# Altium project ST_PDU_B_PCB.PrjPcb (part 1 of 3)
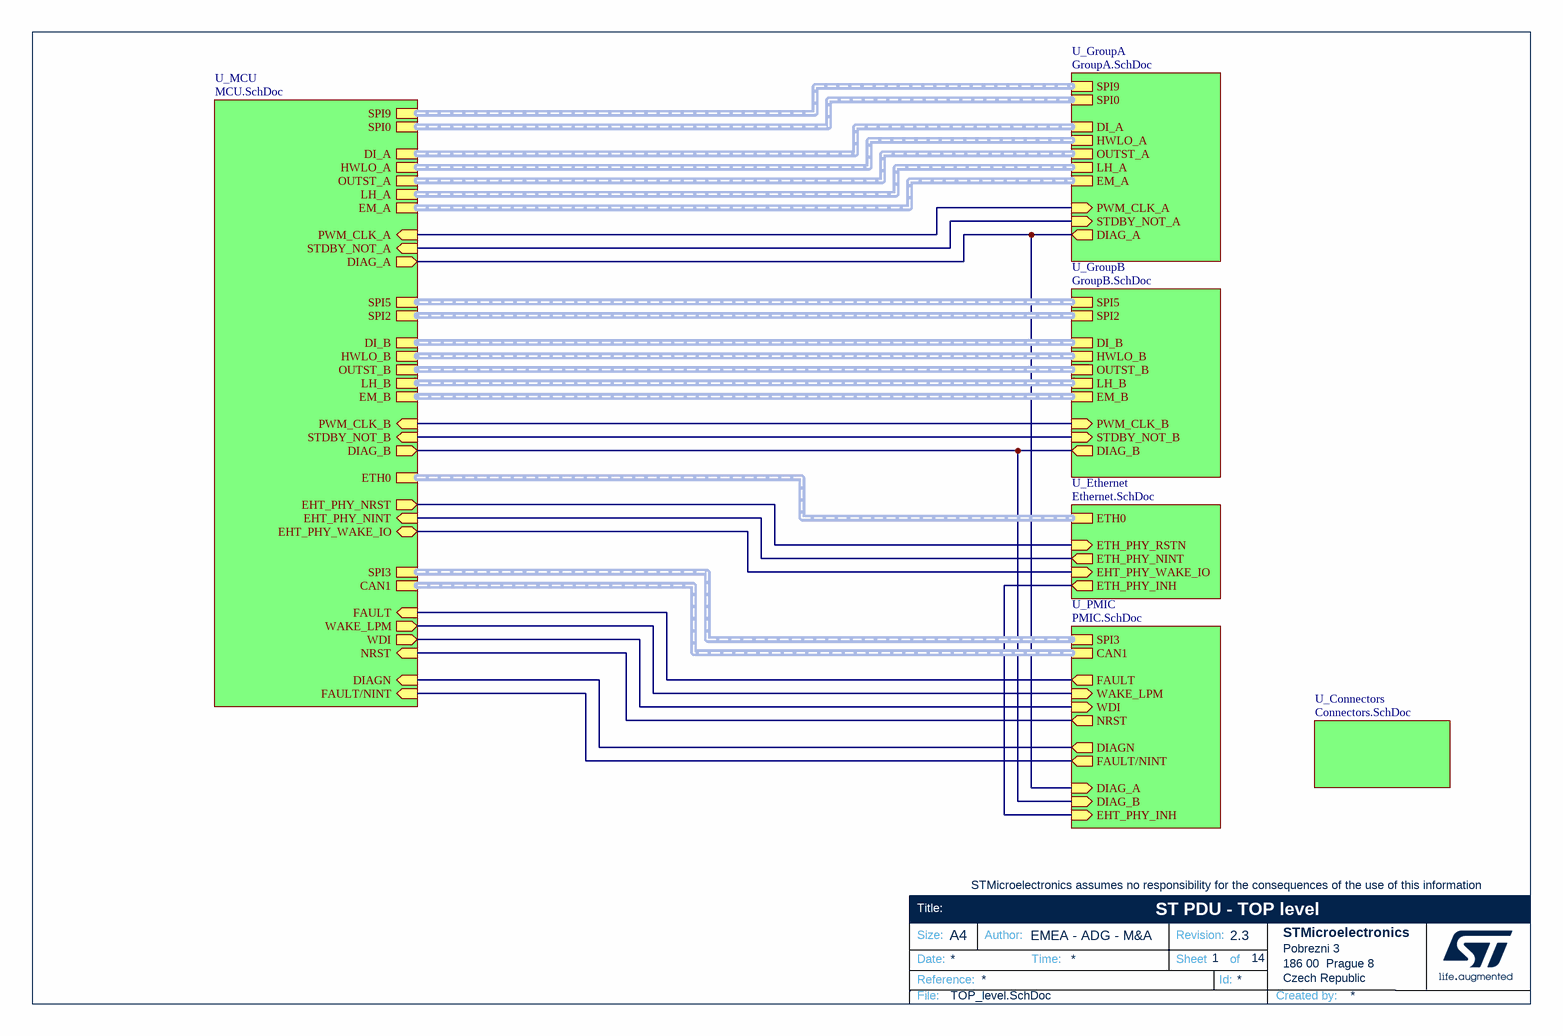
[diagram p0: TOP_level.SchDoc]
14 sheets, 872 parts. Net scope: hierarchical (ports join the sheet entries above them; power ports are global).
Board file: ST_PDU_B_PCB.PcbDoc
Sheets:
  TOP_level.SchDoc
    U_GroupA = GroupA.SchDoc
      U_VNF1248+8F8_A1 = VNF1248+8F8.SchDoc
      U_VNF1248+5F8_A1 = VNF1248+5F8.SchDoc
      U_VNF1248+3F8_A1 = VNF1248+3F8.SchDoc
      U_VNF1248+3F8_A2 = VNF1248+3F8.SchDoc
      U_VNF1248+3F8_A3 = VNF1248+3F8.SchDoc
      U_VNF9D1M5Q_A1 = VNF9D1M5Q.SchDoc
      U_VNF9D1M5Q_A2 = VNF9D1M5Q.SchDoc
      U_L99SP08_A1 = L99SP08.SchDoc
      U_VNF9Q20SF_A1 = VNF9Q20SF.SchDoc
    U_GroupB = GroupB.SchDoc
      U_VNF1248+8F8_B1 = VNF1248+8F8.SchDoc
      U_VNF1248+5F8_B1 = VNF1248+5F8.SchDoc
      U_VNF1248+3F8_B1 = VNF1248+3F8.SchDoc
      U_VNF1248+3F8_B2 = VNF1248+3F8.SchDoc
      U_VNF1248+3F8_B3 = VNF1248+3F8.SchDoc
      U_VNF9D1M5Q_B1 = VNF9D1M5Q.SchDoc
      U_VNF9D1M5Q_B2 = VNF9D1M5Q.SchDoc
      U_L99SP08_B1 = L99SP08.SchDoc
      U_VNF9D5SF_B1 = VNF9D5SF.SchDoc
      U_VNF9D5SF_B2 = VNF9D5SF.SchDoc
    U_MCU = MCU.SchDoc
    U_PMIC = PMIC.SchDoc
    U_Ethernet = Ethernet.SchDoc
    U_Connectors = Connectors.SchDoc

## Sheet TOP_level.SchDoc: ST PDU - TOP level
size A4; Author: EMEA - ADG - M&A; Organization: STMicroelectronics; Address1: Pobrezni 3; Address2: 186 00  Prague 8; Address3: Czech Republic; Revision: 2.3; SheetNumber: 1; SheetTotal: 14

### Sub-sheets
U_Connectors = Connectors.SchDoc: no entries
U_Ethernet = Ethernet.SchDoc: ETH0 (harness ETH0), ETH_PHY_RSTN (in), ETH_PHY_NINT (out), EHT_PHY_WAKE_IO (in), ETH_PHY_INH (out)
U_GroupA = GroupA.SchDoc: SPI9 (harness SPI9), SPI0 (harness SPI0), HWLO_A (harness HWLO_A), DI_A (harness DI_A), OUTST_A (harness OUTST_A), DIAG_A (out), STDBY_NOT_A (in), PWM_CLK_A (in), LH_A (harness LH_A), EM_A (harness EM_A)
U_GroupB = GroupB.SchDoc: SPI2 (harness SPI6), SPI5 (harness SPI5), HWLO_B (harness HWLO_B), DI_B (harness DI_B), OUTST_B (harness OUTST_B), DIAG_B (out), STDBY_NOT_B (in), PWM_CLK_B (in), LH_B (harness LH_B), EM_B (harness EM_B)
U_MCU = MCU.SchDoc: SPI9 (harness SPI9), SPI0 (harness SPI0), HWLO_A (harness HWLO_A), DI_A (harness DI_A), OUTST_A (harness OUTST_A), DIAG_A (out), STDBY_NOT_A (in), PWM_CLK_A (in), LH_A (harness LH_A), EM_A (harness EM_A), SPI2 (harness SPI6), SPI5 (harness SPI5), HWLO_B (harness HWLO_B), DI_B (harness DI_B), OUTST_B (harness OUTST_B), DIAG_B (out), STDBY_NOT_B (in), PWM_CLK_B (in), LH_B (harness LH_B), EM_B (harness EM_B), ETH0 (harness ETH0), SPI3 (harness SPI3), CAN1 (harness CAN1), NRST (in), FAULT (in), WAKE_LPM (out), WDI (out), DIAGN (in), FAULT/NINT (in), EHT_PHY_NRST (out), EHT_PHY_WAKE_IO (bidir), EHT_PHY_NINT (in)
U_PMIC = PMIC.SchDoc: NRST (out), FAULT (out), WAKE_LPM (in), WDI (in), SPI3 (harness SPI3), CAN1 (harness CAN1), DIAGN (out), FAULT/NINT (out), DIAG_A (in), DIAG_B (in), EHT_PHY_INH (in)

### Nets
DIAG_A: sheet U_GroupA/DIAG_A, sheet U_MCU/DIAG_A, sheet U_PMIC/DIAG_A
DIAG_B: sheet U_GroupB/DIAG_B, sheet U_MCU/DIAG_B, sheet U_PMIC/DIAG_B
DIAGN: sheet U_MCU/DIAGN, sheet U_PMIC/DIAGN
ETH_INH: sheet U_PMIC/EHT_PHY_INH, sheet U_Ethernet/ETH_PHY_INH
ETH_PHY_NINT: sheet U_MCU/EHT_PHY_NINT, sheet U_Ethernet/ETH_PHY_NINT
ETH_PHY_NRST: sheet U_MCU/EHT_PHY_NRST, sheet U_Ethernet/ETH_PHY_RSTN
ETH_PHY_WAKE_IO: sheet U_MCU/EHT_PHY_WAKE_IO, sheet U_Ethernet/EHT_PHY_WAKE_IO
FAULT: sheet U_MCU/FAULT, sheet U_PMIC/FAULT
FAULT/NINT: sheet U_MCU/FAULT/NINT, sheet U_PMIC/FAULT/NINT
NRST: sheet U_MCU/NRST, sheet U_PMIC/NRST
PWM_CLK_A: sheet U_GroupA/PWM_CLK_A, sheet U_MCU/PWM_CLK_A
PWM_CLK_B: sheet U_GroupB/PWM_CLK_B, sheet U_MCU/PWM_CLK_B
STDBY_NOT_A: sheet U_GroupA/STDBY_NOT_A, sheet U_MCU/STDBY_NOT_A
STDBY_NOT_B: sheet U_GroupB/STDBY_NOT_B, sheet U_MCU/STDBY_NOT_B
WDI: sheet U_MCU/WDI, sheet U_PMIC/WDI
WK_LPM: sheet U_MCU/WAKE_LPM, sheet U_PMIC/WAKE_LPM

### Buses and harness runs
harness sheet U_Ethernet/ETH0 = sheet U_MCU/ETH0
harness sheet U_GroupA/DI_A = sheet U_MCU/DI_A
harness sheet U_GroupA/EM_A = sheet U_MCU/EM_A
harness sheet U_GroupA/HWLO_A = sheet U_MCU/HWLO_A
harness sheet U_GroupA/LH_A = sheet U_MCU/LH_A
harness sheet U_GroupA/OUTST_A = sheet U_MCU/OUTST_A
harness sheet U_GroupA/SPI0 = sheet U_MCU/SPI0
harness sheet U_GroupA/SPI9 = sheet U_MCU/SPI9
harness sheet U_GroupB/DI_B = sheet U_MCU/DI_B
harness sheet U_GroupB/EM_B = sheet U_MCU/EM_B
harness sheet U_GroupB/HWLO_B = sheet U_MCU/HWLO_B
harness sheet U_GroupB/LH_B = sheet U_MCU/LH_B
harness sheet U_GroupB/OUTST_B = sheet U_MCU/OUTST_B
harness sheet U_GroupB/SPI2 = sheet U_MCU/SPI2
harness sheet U_GroupB/SPI5 = sheet U_MCU/SPI5
harness sheet U_MCU/CAN1 = sheet U_PMIC/CAN1
harness sheet U_MCU/SPI3 = sheet U_PMIC/SPI3

## Sheet GroupA.SchDoc: ST PDU - Group A
size A3; Author: EMEA - ADG - M&A; Organization: STMicroelectronics; Address1: Pobrezni 3; Address2: 186 00  Prague 8; Address3: Czech Republic; Revision: 2.3; SheetNumber: 2; SheetTotal: 14
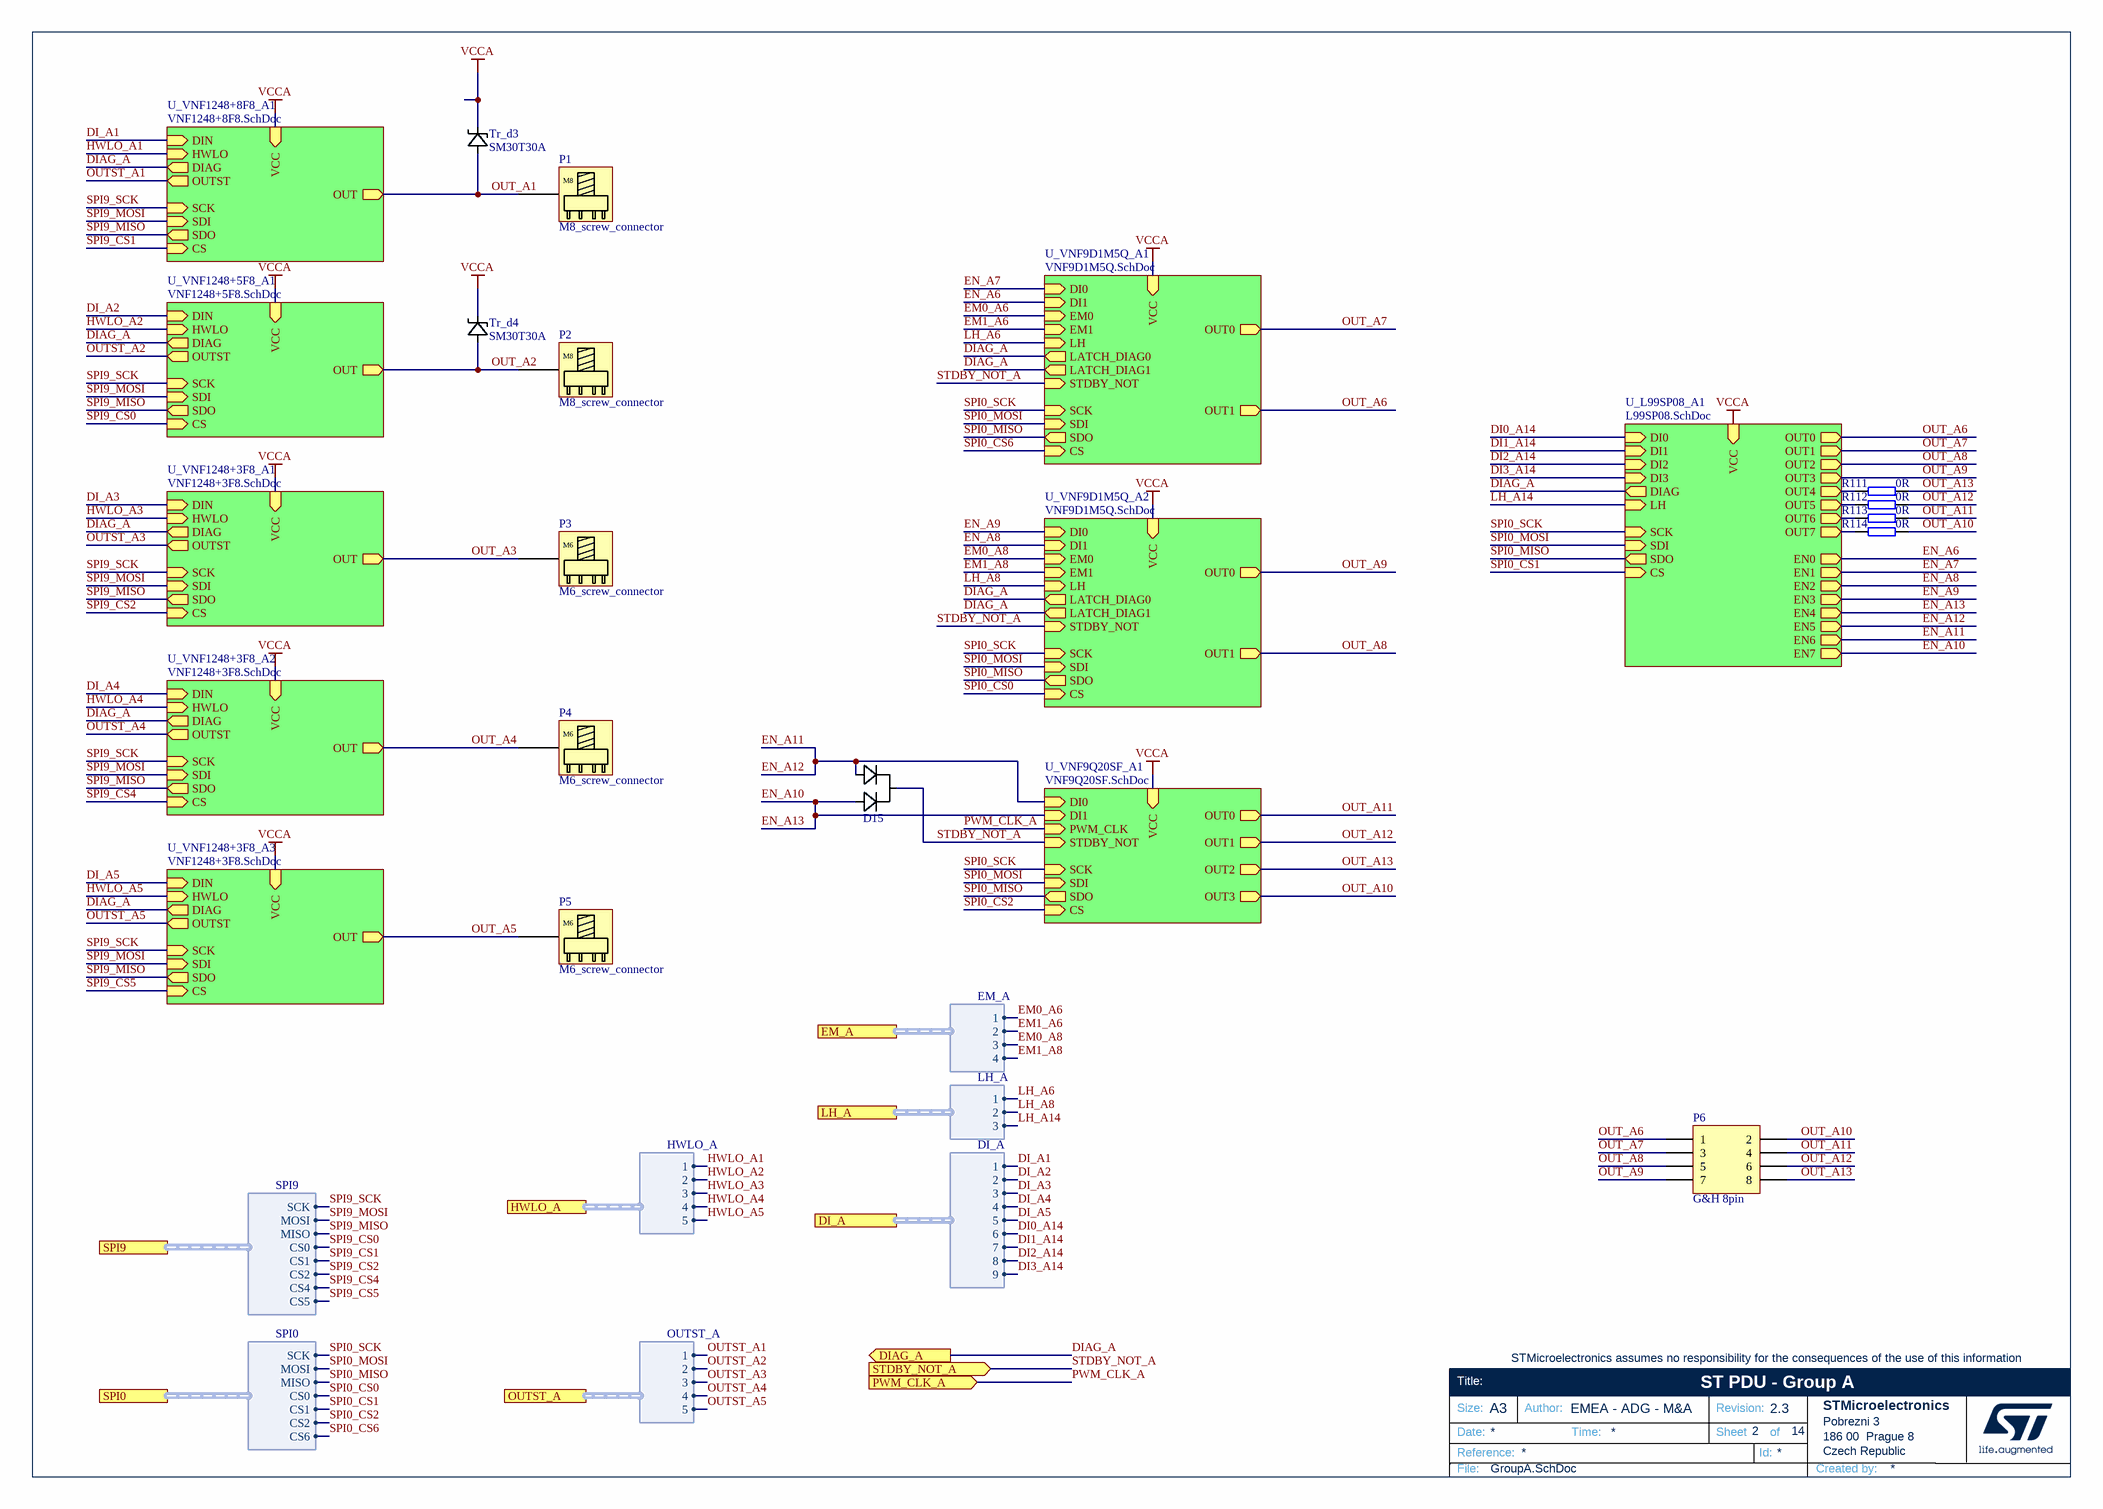
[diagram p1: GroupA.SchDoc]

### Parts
D15  BAT54-Y  [SOT323-3L_STM]  (value not drawn)
P1  M8_screw_connector  [MTConn Power Tower M8]
P2  M8_screw_connector  [MTConn Power Tower M8]
P3  M6_screw_connector  [MTConn Power Tower M6]
P4  M6_screw_connector  [MTConn Power Tower M6]
P5  M6_screw_connector  [MTConn Power Tower M6]
P6  value G&H 8pin  [MTConn GH 8pin]  (hidden comment: GH 8pin)
R111  0R  [R0603_round]
R112  0R  [R0603_round]
R113  0R  [R0603_round]
R114  0R  [R0603_round]
Tr_d3  SM30T30A  [SMC]
Tr_d4  SM30T30A  [SMC]

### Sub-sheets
U_L99SP08_A1 = L99SP08.SchDoc: CS (in), SCK (in), SDI (in), SDO (out), OUT1 (out), OUT2 (out), OUT3 (out), OUT0 (out), DI0 (in), DI1 (in), DI2 (in), DI3 (in), LH (in), DIAG (out), VCC (in), EN1 (out), EN2 (out), EN3 (out), EN0 (out), EN5 (out), EN6 (out), EN7 (out), EN4 (out), OUT5 (out), OUT6 (out), OUT7 (out), OUT4 (out)
U_VNF9D1M5Q_A1 = VNF9D1M5Q.SchDoc: CS (in), OUT0 (out), OUT1 (out), SCK (in), SDI (in), SDO (out), EM0 (in), EM1 (in), DI0 (in), DI1 (in), LATCH_DIAG0 (out), LATCH_DIAG1 (out), LH (in), VCC (in), STDBY_NOT (in)
U_VNF9D1M5Q_A2 = VNF9D1M5Q.SchDoc: CS (in), OUT0 (out), OUT1 (out), SCK (in), SDI (in), SDO (out), EM0 (in), EM1 (in), DI0 (in), DI1 (in), LATCH_DIAG0 (out), LATCH_DIAG1 (out), LH (in), VCC (in), STDBY_NOT (in)
U_VNF9Q20SF_A1 = VNF9Q20SF.SchDoc: CS (in), SCK (in), SDI (in), SDO (out), OUT0 (out), OUT3 (out), OUT2 (out), OUT1 (out), DI0 (in), DI1 (in), PWM_CLK (in), STDBY_NOT (in), VCC (in)
U_VNF1248+3F8_A1 = VNF1248+3F8.SchDoc: OUT (out), VCC (in), CS (in), SCK (in), SDI (in), SDO (out), DIAG (out), HWLO (in), DIN (in), OUTST (out)
U_VNF1248+3F8_A2 = VNF1248+3F8.SchDoc: OUT (out), VCC (in), CS (in), SCK (in), SDI (in), SDO (out), DIAG (out), HWLO (in), DIN (in), OUTST (out)
U_VNF1248+3F8_A3 = VNF1248+3F8.SchDoc: OUT (out), VCC (in), CS (in), SCK (in), SDI (in), SDO (out), DIAG (out), HWLO (in), DIN (in), OUTST (out)
U_VNF1248+5F8_A1 = VNF1248+5F8.SchDoc: OUT (out), VCC (in), CS (in), SCK (in), SDI (in), SDO (out), DIAG (out), HWLO (in), DIN (in), OUTST (out)
U_VNF1248+8F8_A1 = VNF1248+8F8.SchDoc: OUT (out), VCC (in), CS (in), SCK (in), SDI (in), SDO (out), DIAG (out), HWLO (in), DIN (in), OUTST (out)

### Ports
DI_A (harness DI_A, see TOP_level[3A], MCU[1A]), DIAG_A (out, see TOP_level[3A], MCU[1B], PMIC[3D]), EM_A (harness EM_A, see TOP_level[3A], MCU[1A]), HWLO_A (harness HWLO_A, see TOP_level[3A], MCU[1B]), LH_A (harness LH_A, see TOP_level[3A], MCU[1A]), OUTST_A (harness OUTST_A, see TOP_level[3A], MCU[1B]), PWM_CLK_A (in, see TOP_level[3A], MCU[1B]), SPI0 (harness SPI0, see TOP_level[3A], MCU[1D]), SPI9 (harness SPI9, see TOP_level[3A], MCU[1D]), STDBY_NOT_A (in, see TOP_level[3A], MCU[1B])

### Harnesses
SPI9: SCK, MOSI, MISO, CS0, CS1, CS2, CS4, CS5
SPI0: SCK, MOSI, MISO, CS0, CS1, CS2, CS6
HWLO_A: 1, 2, 3, 4, 5
DI_A: 1, 2, 3, 4, 5, 6, 7, 8, 9
OUTST_A: 1, 2, 3, 4, 5
LH_A: 1, 2, 3
EM_A: 1, 2, 3, 4

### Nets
VCCA: Tr_d3.C Tr_d4.C ; sheet U_VNF1248+8F8_A1/VCC, sheet U_VNF1248+5F8_A1/VCC, sheet U_VNF1248+3F8_A1/VCC, sheet U_VNF1248+3F8_A2/VCC, sheet U_VNF1248+3F8_A3/VCC, sheet U_VNF9D1M5Q_A1/VCC, sheet U_VNF9D1M5Q_A2/VCC, sheet U_L99SP08_A1/VCC, sheet U_VNF9Q20SF_A1/VCC
DI0_A14: sheet U_L99SP08_A1/DI0, port DI_A.6
DI1_A14: sheet U_L99SP08_A1/DI1, port DI_A.7
DI2_A14: sheet U_L99SP08_A1/DI2, port DI_A.8
DI3_A14: sheet U_L99SP08_A1/DI3, port DI_A.9
DI_A1: sheet U_VNF1248+8F8_A1/DIN, port DI_A.1
DI_A2: sheet U_VNF1248+5F8_A1/DIN, port DI_A.2
DI_A3: sheet U_VNF1248+3F8_A1/DIN, port DI_A.3
DI_A4: sheet U_VNF1248+3F8_A2/DIN, port DI_A.4
DI_A5: sheet U_VNF1248+3F8_A3/DIN, port DI_A.5
DIAG_A: port DIAG_A, sheet U_VNF1248+8F8_A1/DIAG, sheet U_VNF1248+5F8_A1/DIAG, sheet U_VNF1248+3F8_A1/DIAG, sheet U_VNF1248+3F8_A2/DIAG, sheet U_VNF1248+3F8_A3/DIAG, sheet U_VNF9D1M5Q_A1/LATCH_DIAG0, sheet U_VNF9D1M5Q_A1/LATCH_DIAG1, sheet U_VNF9D1M5Q_A2/LATCH_DIAG0, sheet U_VNF9D1M5Q_A2/LATCH_DIAG1, sheet U_L99SP08_A1/DIAG
EM0_A6: sheet U_VNF9D1M5Q_A1/EM0, port EM_A.1
EM0_A8: sheet U_VNF9D1M5Q_A2/EM0, port EM_A.3
EM1_A6: sheet U_VNF9D1M5Q_A1/EM1, port EM_A.2
EM1_A8: sheet U_VNF9D1M5Q_A2/EM1, port EM_A.4
EN_A6: sheet U_VNF9D1M5Q_A1/DI1, sheet U_L99SP08_A1/EN0
EN_A7: sheet U_VNF9D1M5Q_A1/DI0, sheet U_L99SP08_A1/EN1
EN_A8: sheet U_VNF9D1M5Q_A2/DI1, sheet U_L99SP08_A1/EN2
EN_A9: sheet U_VNF9D1M5Q_A2/DI0, sheet U_L99SP08_A1/EN3
EN_A10: D15.1 ; sheet U_L99SP08_A1/EN7, sheet U_L99SP08_A1/EN4, sheet U_VNF9Q20SF_A1/DI1  [also labelled EN_A13]
EN_A11: D15.2 ; sheet U_L99SP08_A1/EN5, sheet U_L99SP08_A1/EN6, sheet U_VNF9Q20SF_A1/DI0  [also labelled EN_A12]
HWLO_A1: sheet U_VNF1248+8F8_A1/HWLO, port HWLO_A.1
HWLO_A2: sheet U_VNF1248+5F8_A1/HWLO, port HWLO_A.2
HWLO_A3: sheet U_VNF1248+3F8_A1/HWLO, port HWLO_A.3
HWLO_A4: sheet U_VNF1248+3F8_A2/HWLO, port HWLO_A.4
HWLO_A5: sheet U_VNF1248+3F8_A3/HWLO, port HWLO_A.5
LH_A6: sheet U_VNF9D1M5Q_A1/LH, port LH_A.1
LH_A8: sheet U_VNF9D1M5Q_A2/LH, port LH_A.2
LH_A14: sheet U_L99SP08_A1/LH, port LH_A.3
OUT_A1: P1.1 Tr_d3.A ; sheet U_VNF1248+8F8_A1/OUT
OUT_A2: P2.1 Tr_d4.A ; sheet U_VNF1248+5F8_A1/OUT
OUT_A3: P3.1 ; sheet U_VNF1248+3F8_A1/OUT
OUT_A4: P4.1 ; sheet U_VNF1248+3F8_A2/OUT
OUT_A5: P5.1 ; sheet U_VNF1248+3F8_A3/OUT
OUT_A6: P6.1 ; sheet U_VNF9D1M5Q_A1/OUT1, sheet U_L99SP08_A1/OUT0
OUT_A7: P6.3 ; sheet U_VNF9D1M5Q_A1/OUT0, sheet U_L99SP08_A1/OUT1
OUT_A8: P6.5 ; sheet U_VNF9D1M5Q_A2/OUT1, sheet U_L99SP08_A1/OUT2
OUT_A9: P6.7 ; sheet U_VNF9D1M5Q_A2/OUT0, sheet U_L99SP08_A1/OUT3
OUT_A10: P6.2 R114.1 ; sheet U_VNF9Q20SF_A1/OUT3
OUT_A11: P6.4 R113.1 ; sheet U_VNF9Q20SF_A1/OUT0
OUT_A12: P6.6 R112.1 ; sheet U_VNF9Q20SF_A1/OUT1
OUT_A13: P6.8 R111.1 ; sheet U_VNF9Q20SF_A1/OUT2
OUTST_A1: sheet U_VNF1248+8F8_A1/OUTST, port OUTST_A.1
OUTST_A2: sheet U_VNF1248+5F8_A1/OUTST, port OUTST_A.2
OUTST_A3: sheet U_VNF1248+3F8_A1/OUTST, port OUTST_A.3
OUTST_A4: sheet U_VNF1248+3F8_A2/OUTST, port OUTST_A.4
OUTST_A5: sheet U_VNF1248+3F8_A3/OUTST, port OUTST_A.5
PWM_CLK_A: port PWM_CLK_A, sheet U_VNF9Q20SF_A1/PWM_CLK
SPI0_CS0: sheet U_VNF9D1M5Q_A2/CS, port SPI0.CS0
SPI0_CS1: sheet U_L99SP08_A1/CS, port SPI0.CS1
SPI0_CS2: sheet U_VNF9Q20SF_A1/CS, port SPI0.CS2
SPI0_CS6: sheet U_VNF9D1M5Q_A1/CS, port SPI0.CS6
SPI0_MISO: sheet U_VNF9D1M5Q_A1/SDO, sheet U_VNF9D1M5Q_A2/SDO, sheet U_L99SP08_A1/SDO, sheet U_VNF9Q20SF_A1/SDO, port SPI0.MISO
SPI0_MOSI: sheet U_VNF9D1M5Q_A1/SDI, sheet U_VNF9D1M5Q_A2/SDI, sheet U_L99SP08_A1/SDI, sheet U_VNF9Q20SF_A1/SDI, port SPI0.MOSI
SPI0_SCK: sheet U_VNF9D1M5Q_A1/SCK, sheet U_VNF9D1M5Q_A2/SCK, sheet U_L99SP08_A1/SCK, sheet U_VNF9Q20SF_A1/SCK, port SPI0.SCK
SPI9_CS0: sheet U_VNF1248+5F8_A1/CS, port SPI9.CS0
SPI9_CS1: sheet U_VNF1248+8F8_A1/CS, port SPI9.CS1
SPI9_CS2: sheet U_VNF1248+3F8_A1/CS, port SPI9.CS2
SPI9_CS4: sheet U_VNF1248+3F8_A2/CS, port SPI9.CS4
SPI9_CS5: sheet U_VNF1248+3F8_A3/CS, port SPI9.CS5
SPI9_MISO: sheet U_VNF1248+8F8_A1/SDO, sheet U_VNF1248+5F8_A1/SDO, sheet U_VNF1248+3F8_A1/SDO, sheet U_VNF1248+3F8_A2/SDO, sheet U_VNF1248+3F8_A3/SDO, port SPI9.MISO
SPI9_MOSI: sheet U_VNF1248+8F8_A1/SDI, sheet U_VNF1248+5F8_A1/SDI, sheet U_VNF1248+3F8_A1/SDI, sheet U_VNF1248+3F8_A2/SDI, sheet U_VNF1248+3F8_A3/SDI, port SPI9.MOSI
SPI9_SCK: sheet U_VNF1248+8F8_A1/SCK, sheet U_VNF1248+5F8_A1/SCK, sheet U_VNF1248+3F8_A1/SCK, sheet U_VNF1248+3F8_A2/SCK, sheet U_VNF1248+3F8_A3/SCK, port SPI9.SCK
STDBY_NOT_A: D15.3 ; port STDBY_NOT_A, sheet U_VNF9D1M5Q_A1/STDBY_NOT, sheet U_VNF9D1M5Q_A2/STDBY_NOT, sheet U_VNF9Q20SF_A1/STDBY_NOT
NetR111_2: R111.2 ; sheet U_L99SP08_A1/OUT4
NetR112_2: R112.2 ; sheet U_L99SP08_A1/OUT5
NetR113_2: R113.2 ; sheet U_L99SP08_A1/OUT6
NetR114_2: R114.2 ; sheet U_L99SP08_A1/OUT7

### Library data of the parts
D15 = BAT54C: Automotive small signal dual Schottky diodes with common cathode; Forward Drop: 0,5V; T.Min: -40C; T.Max: 150C; Value: 40V; Current: 0.3A
P1 P2 = M8_screw_connector: Pressfit M8 screw power connector (max 170A) with protector
P3-P5 = M6_screw_connector: Pressfit M6 screw power connector (max 80A) with protector
P6 = GH 8pin: MTCon G&H 8pin power connector (max 40A/pin). Pressfit; Model: TSW-110-07-G-S
R111-R114 = 0R/0.1W_5%_0603: Resistor SMD; Tolerance: 5%; Power: 0.1W
Tr_d3 Tr_d4 = SM30T30A: 30V 3000W unidirectional TVS in SMC; T.Min: -55C; T.Max: +150C

## Sheet VNF1248+8F8.SchDoc: ST PDU - VNF1248 + 8xF8
size A4; Author: EMEA - ADG - M&A; Organization: STMicroelectronics; Address1: Pobrezni 3; Address2: 186 00  Prague 8; Address3: Czech Republic; Revision: 2.3; SheetNumber: 3; SheetTotal: 14
Used 2 times, as channels U_GroupA/U_VNF1248+8F8_A1, U_GroupB/U_VNF1248+8F8_B1. Parts and nets are listed once, with the designators drawn on the sheet.
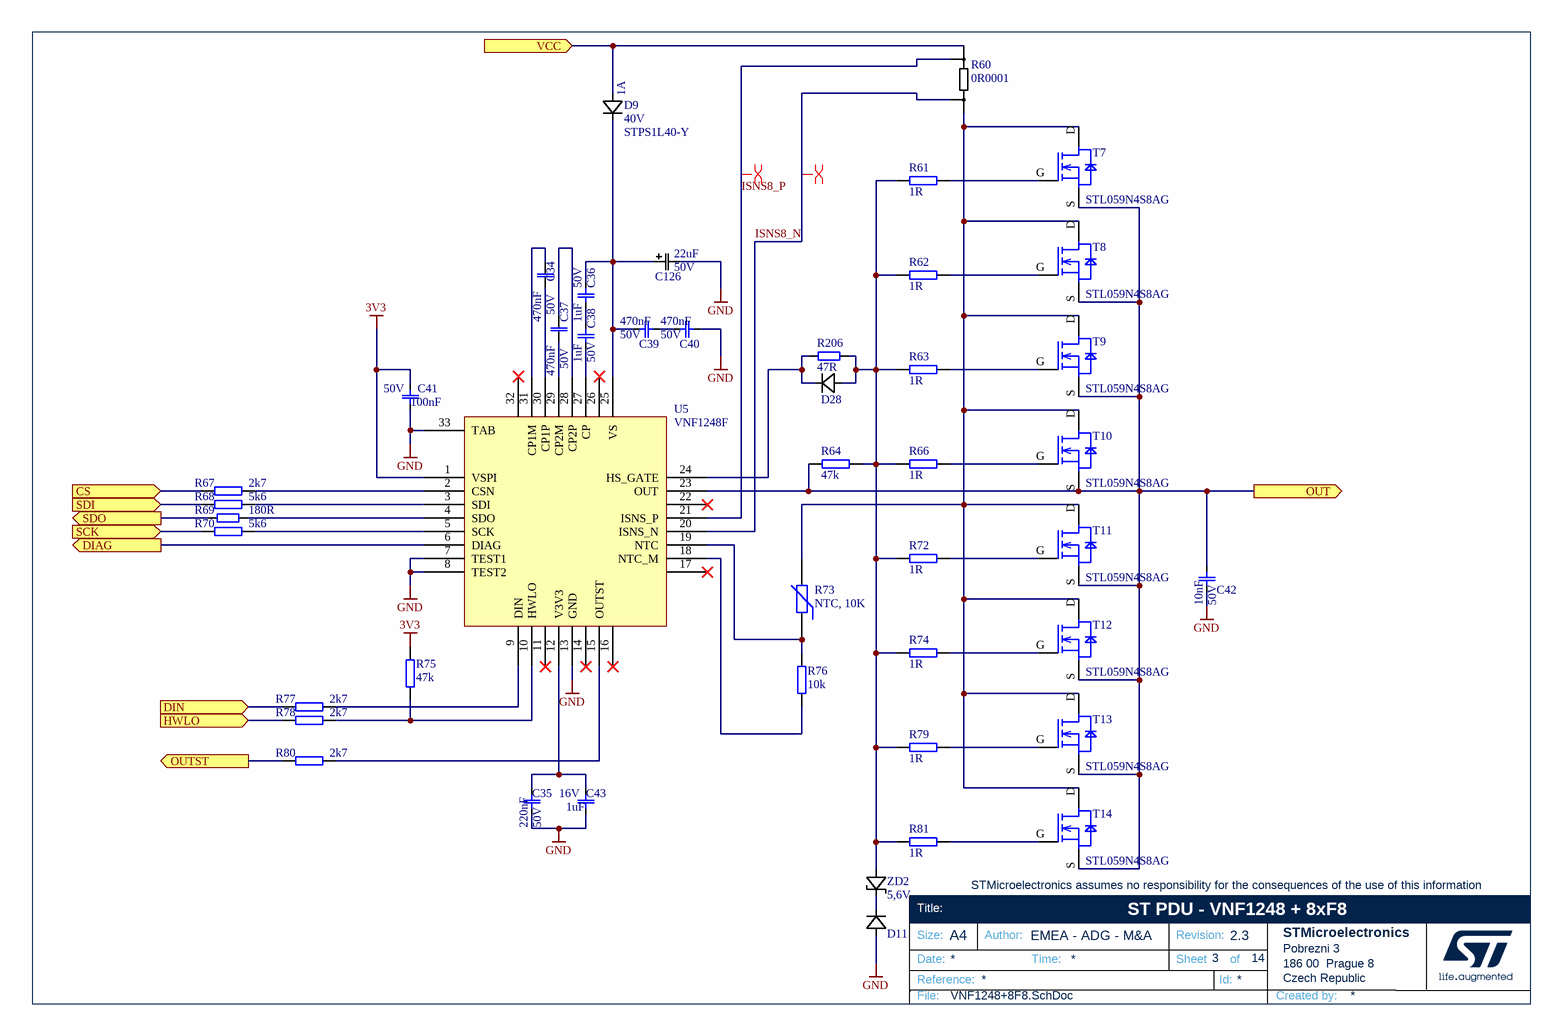
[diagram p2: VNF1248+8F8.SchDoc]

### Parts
C34  Voltage: 50V  [C0603_ROUND]  (hidden comment: 470nF)
C35  Voltage: 50V  [C0603_ROUND]  (hidden comment: 220nF)
C36  Voltage: 50V  [C0603_ROUND]  (hidden comment: 1uF)
C37  Voltage: 50V  [C0603_ROUND]  (hidden comment: 470nF)
C38  Voltage: 50V  [C0603_ROUND]  (hidden comment: 1uF)
C39  Voltage: 50V  [C0603_ROUND]  (hidden comment: 470nF)
C40  Voltage: 50V  [C0603_ROUND]  (hidden comment: 470nF)
C41  Voltage: 50V  [C0603_ROUND]  (hidden comment: 100nF)
C42  Voltage: 50V  [C0603_ROUND]  (hidden comment: 10nF)
C43  Voltage: 16V  [C0603_ROUND]  (hidden comment: 1uF)
C126  Voltage: 50V  [C_EL 6.3x6.1mm VP]  (hidden comment: 22uF)
D9  value 40V  Current: 1A  [SOD123FLAT_STM]  (hidden comment: STPS1L40-Y)
D11  BAT54-Y  [SOT323-3L_STM]  (value not drawn)
D28  BAT54-Y  [SOT323-3L_STM]  (value not drawn)
R60  0R0001  [R Shunt 5930]
R61  1R  [R0603_round]
R62  1R  [R0603_round]
R63  1R  [R0603_round]
R64  47k  [R0603_round]
R66  1R  [R0603_round]
R67  2k7  [R0603_round]
R68  5k6  [R0603_round]
R69  180R  [R0603_round]
R70  5k6  [R0603_round]
R72  1R  [R0603_round]
R73  value NTC, 10K  [R0603_round]  (hidden comment: NTC)
R74  1R  [R0603_round]
R75  47k  [R0603_round]
R76  10k  [R0603_round]
R77  2k7  [R0603_round]
R78  2k7  [R0603_round]
R79  1R  [R0603_round]
R80  2k7  [R0603_round]
R81  1R  [R0603_round]
R206  47R  [R0603_round]
T7  value STL059N4S8AG  [Powerflat_5x6_Single_island]  (hidden comment: NMOS)
T8  value STL059N4S8AG  [Powerflat_5x6_Single_island]  (hidden comment: NMOS)
T9  value STL059N4S8AG  [Powerflat_5x6_Single_island]  (hidden comment: NMOS)
T10  value STL059N4S8AG  [Powerflat_5x6_Single_island]  (hidden comment: NMOS)
T11  value STL059N4S8AG  [Powerflat_5x6_Single_island]  (hidden comment: NMOS)
T12  value STL059N4S8AG  [Powerflat_5x6_Single_island]  (hidden comment: NMOS)
T13  value STL059N4S8AG  [Powerflat_5x6_Single_island]  (hidden comment: NMOS)
T14  value STL059N4S8AG  [Powerflat_5x6_Single_island]  (hidden comment: NMOS)
U5  VNF1248F  [QFN32L_5x5_STM-M]
ZD2  value 5,6V  [SOT323-3L_STM]  (hidden comment: 5,6V/SOT-323)

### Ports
CS (in, see GroupA[1A]), DIAG (out, see GroupA[1A], L99SP08[1B], VNF1248+3F8[1C], VNF1248+5F8[1C]), DIN (in, see GroupA[1A]), HWLO (in, see GroupA[1A]), OUT (out, see GroupA[2A]), OUTST (out, see GroupA[1A]), SCK (in, see GroupA[1A], VNF1248+3F8[1C], VNF1248+5F8[1C]), SDI (in, see GroupA[1A], VNF1248+3F8[1B], VNF1248+5F8[1B]), SDO (out, see GroupA[1A], VNF1248+3F8[1C], VNF1248+5F8[1C]), VCC (in, see GroupA[2A], L99SP08[2A], VNF9D1M5Q[3A], VNF9Q20SF[3A], VNF1248+3F8[3A], VNF1248+5F8[3A])

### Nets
3V3: C41.2 R75.1 U5.1(VSPI)
GND: C35.1 C40.2 C41.1 C42.1 C43.1 C126.2 D11.A U5.7(TEST1) U5.8(TEST2) U5.13(GND) U5.33(TAB)
CS: R67.2 ; port CS
DIAG: U5.6(DIAG) ; port DIAG
DIN: R77.2 ; port DIN
HWLO: R78.2 ; port HWLO
ISNS8_N: R60.3 U5.20(ISNS_N)
ISNS8_P: R60.4 U5.21(ISNS_P)
OUT: C42.2 R64.2 T7.S T8.S T9.S T10.S T11.S T12.S T13.S T14.S U5.23(OUT) ; port OUT
OUTST: R80.2 ; port OUTST
SCK: R70.2 ; port SCK
SDI: R68.2 ; port SDI
SDO: R69.2 ; port SDO
VCC: D9.A R60.2 ; port VCC
NetC34_1: C34.1 U5.30(CP1P)
NetC34_2: C34.2 U5.31(CP1M)
NetC35_2: C35.2 C43.2 U5.12(V3V3)
NetC36_1: C36.1 C38.2
NetC36_2: C36.2 C39.1 C126.1 D9.C U5.25(VS)
NetC37_1: C37.1 U5.29(CP2M)
NetC37_2: C37.2 U5.28(CP2P)
NetC38_1: C38.1 U5.27(CP)
NetC39_2: C39.2 C40.1
NetD11_C: D11.C ZD2.C
NetD28_A: D28.A R61.1 R62.1 R63.1 R64.1 R66.1 R72.1 R74.1 R79.1 R81.1 R206.2 ZD2.A
NetD28_C: D28.C R206.1 U5.24(HS_GATE)
NetR60_1: R60.1 R73.2 T7.D T8.D T9.D T10.D T11.D T12.D T13.D T14.D
NetR61_2: R61.2 T7.G
NetR62_2: R62.2 T8.G
NetR63_2: R63.2 T9.G
NetR66_2: R66.2 T10.G
NetR67_1: R67.1 U5.2(CSN)
NetR68_1: R68.1 U5.3(SDI)
NetR69_1: R69.1 U5.4(SDO)
NetR70_1: R70.1 U5.5(SCK)
NetR72_2: R72.2 T11.G
NetR73_1: R73.1 R76.2 U5.19(NTC)
NetR74_2: R74.2 T12.G
NetR75_2: R75.2 R78.1 U5.10(HWLO)
NetR76_1: R76.1 U5.18(NTC_M)
NetR77_1: R77.1 U5.9(DIN)
NetR79_2: R79.2 T13.G
NetR80_1: R80.1 U5.15(OUTST)
NetR81_2: R81.2 T14.G

Not connected (* = marked no-connect by the designer): U5 11* 14* 16* 17* 22* 26* 32*

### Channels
U_GroupA/U_VNF1248+8F8_A1: designators end in A; ports CS=SPI9_CS1 DIAG=DIAG_A DIN=DI_A1 HWLO=HWLO_A1 OUT=OUT_A1 OUTST=OUTST_A1 SCK=SPI9_SCK SDI=SPI9_MOSI SDO=SPI9_MISO VCC=VCCA
U_GroupB/U_VNF1248+8F8_B1: designators end in B; ports CS=SPI2_CS0 DIAG=DIAG_B DIN=DI_B1 HWLO=HWLO_B1 OUT=OUT_B1 OUTST=OUTST_B1 SCK=SPI2_SCK SDI=SPI2_MOSI SDO=SPI2_MISO VCC=VCCB

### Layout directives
differential pair: ISNS8_N_U_VNF1248+8F8_A1, ISNS8_P_U_VNF1248+8F8_A1

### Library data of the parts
C34 C37 C39 C40 = 470nF/50V_10%_0603: 470nF Ceramic capacitor; Tolerance: 10%; T.Min: -55C; T.Max: 125C; Type: X7R
C35 = 220nF/50V_10%_0603: 220nF Ceramic capacitor; Tolerance: 10%; T.Min: -55C; T.Max: 125C; Type: X7R
C36 C38 = 1uF/50V_10%_0603: 1uF Ceramic capacitor; Tolerance: 10%; T.Min: -55C; T.Max: 125C; Type: X7R
C41 = 100nF/50V_10%_0603: 100nF Ceramic capacitor; Tolerance: 10%; T.Min: -55C; T.Max: 125C; Type: X7R
C42 = 10nF/50V_10%_0603: 10nF Ceramic capacitor; Tolerance: 10%; T.Min: -55C; T.Max: 125C; Type: X7R
C43 = 1uF/16V_10%_0603: 1uF Ceramic capacitor; Tolerance: 10%; T.Min: -55C; T.Max: 125C; Type: X7R
C126 = 22uF/50V_20%_CES_D_6.3: 22uF Electrolytic capacitor (EEHZC1H220V); Tolerance: 20%; T.Min: -55C; T.Max: 125C; Type: Conductive Polymer Hybrid Aluminum Electrolytic Capacitor
D9 = STPS1L40-Y: 40V/1A Automotive Schottky Diode STPS1L40-Y
D11 D28 = BAT54-Y: Automotive small signal Schottky diodes; pin to pad: A>1 C>3; Forward Drop: 0,5V; T.Min: -40C; T.Max: 150C; Value: 40V; Current: 0.3A
R60 = CurrentShunt_15W_5930: ISA-WELD precission resistor  BVE size 5630; Voltage: 150V; Power Rating Per Resistor: 15W; T.Min: -55C; T.Max: 170C
R61-R63 R66 R72 R74 R79 R81 = 1R/0.1W_5%_0603: Resistor SMD; Tolerance: 5%; Power: 0.1W
R64 R75 = 47k/0.1W_5%_0603: Resistor SMD; Tolerance: 5%; Power: 0.1W
R67 R77 R78 R80 = 2k7/0.1W_5%_0603: Resistor SMD; Tolerance: 5%; Power: 0.1W
R68 R70 = 5k6/0.1W_5%_0603: Resistor SMD; Tolerance: 5%; Power: 0.1W
R69 = 180R/0.1W_5%_0603: Resistor SMD 0603; Tolerance: 5%; Power: 0.1W
R73 = NTC: Model: B57321V2103J060
R76 = 10k/0.1W_5%_0603: SMD Resistor Automotive; 2B Part Number: 2BRESCHIPSF00800; Manufacturer: PANASONIC; Manufacturer P/N: ERJP03F1002V; Tolerance: 1%; Power: 0.1W
R206 = 47R/0.1W_5%_0603: Resistor SMD 0603; Tolerance: 5%; Power: 0.1W
T7-T14 = STL059N4S8AG: Automotive N‑channel logic level 40 V, 0.59 mΩ max., 420 A Smart STripFET F8 / Power MOSFET in a PowerFLAT 5x6 package
ZD2 = 5,6V/SOT-323: 5,6V Zener Diode; pin to pad: A>1 C>3; Power Rating: 200mW; T.Min: -65C; T.Max: 200C

## Sheet VNF1248+5F8.SchDoc: ST PDU - VNF1248 + 5xF8
size A4; Author: EMEA - ADG - M&A; Organization: STMicroelectronics; Address1: Pobrezni 3; Address2: 186 00  Prague 8; Address3: Czech Republic; Revision: 2.3; SheetNumber: 4; SheetTotal: 14
Used 2 times, as channels U_GroupA/U_VNF1248+5F8_A1, U_GroupB/U_VNF1248+5F8_B1. Parts and nets are listed once, with the designators drawn on the sheet.
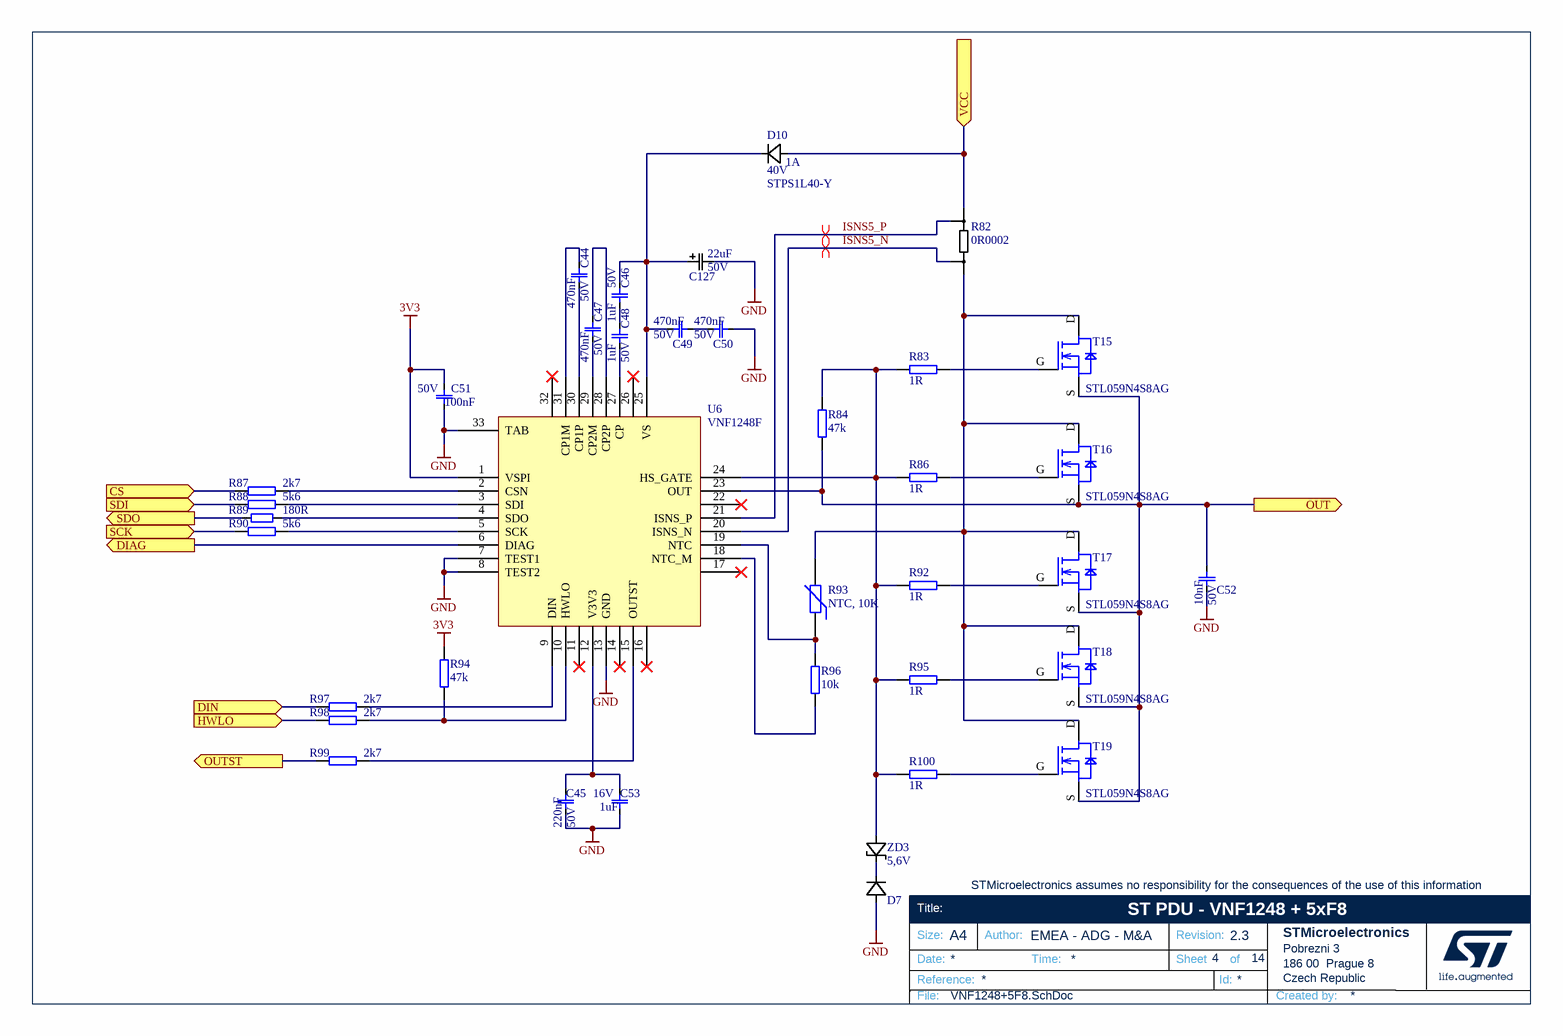
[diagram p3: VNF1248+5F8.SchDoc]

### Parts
C44  Voltage: 50V  [C0603_ROUND]  (hidden comment: 470nF)
C45  Voltage: 50V  [C0603_ROUND]  (hidden comment: 220nF)
C46  Voltage: 50V  [C0603_ROUND]  (hidden comment: 1uF)
C47  Voltage: 50V  [C0603_ROUND]  (hidden comment: 470nF)
C48  Voltage: 50V  [C0603_ROUND]  (hidden comment: 1uF)
C49  Voltage: 50V  [C0603_ROUND]  (hidden comment: 470nF)
C50  Voltage: 50V  [C0603_ROUND]  (hidden comment: 470nF)
C51  Voltage: 50V  [C0603_ROUND]  (hidden comment: 100nF)
C52  Voltage: 50V  [C0603_ROUND]  (hidden comment: 10nF)
C53  Voltage: 16V  [C0603_ROUND]  (hidden comment: 1uF)
C127  Voltage: 50V  [C_EL 6.3x6.1mm VP]  (hidden comment: 22uF)
D7  BAT54-Y  [SOT323-3L_STM]  (value not drawn)
D10  value 40V  Current: 1A  [SOD123FLAT_STM]  (hidden comment: STPS1L40-Y)
R82  0R0002  [R Shunt 5930]
R83  1R  [R0603_round]
R84  47k  [R0603_round]
R86  1R  [R0603_round]
R87  2k7  [R0603_round]
R88  5k6  [R0603_round]
R89  180R  [R0603_round]
R90  5k6  [R0603_round]
R92  1R  [R0603_round]
R93  value NTC, 10K  [R0603_round]  (hidden comment: NTC)
R94  47k  [R0603_round]
R95  1R  [R0603_round]
R96  10k  [R0603_round]
R97  2k7  [R0603_round]
R98  2k7  [R0603_round]
R99  2k7  [R0603_round]
R100  1R  [R0603_round]
T15  value STL059N4S8AG  [Powerflat_5x6_Single_island]  (hidden comment: NMOS)
T16  value STL059N4S8AG  [Powerflat_5x6_Single_island]  (hidden comment: NMOS)
T17  value STL059N4S8AG  [Powerflat_5x6_Single_island]  (hidden comment: NMOS)
T18  value STL059N4S8AG  [Powerflat_5x6_Single_island]  (hidden comment: NMOS)
T19  value STL059N4S8AG  [Powerflat_5x6_Single_island]  (hidden comment: NMOS)
U6  VNF1248F  [QFN32L_5x5_STM-M]
ZD3  value 5,6V  [SOT323-3L_STM]  (hidden comment: 5,6V/SOT-323)

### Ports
CS (in, see GroupA[1B]), DIAG (out, see GroupA[1A], L99SP08[1B], VNF1248+3F8[1C], VNF1248+8F8[1C]), DIN (in, see GroupA[1A]), HWLO (in, see GroupA[1A]), OUT (out, see GroupA[2A]), OUTST (out, see GroupA[1A]), SCK (in, see GroupA[1B], VNF1248+3F8[1C], VNF1248+8F8[1C]), SDI (in, see GroupA[1B], VNF1248+3F8[1B], VNF1248+8F8[1B]), SDO (out, see GroupA[1B], VNF1248+3F8[1C], VNF1248+8F8[1C]), VCC (in, see GroupA[2A], L99SP08[2A], VNF9D1M5Q[3A], VNF9Q20SF[3A], VNF1248+3F8[3A], VNF1248+8F8[2A])

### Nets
3V3: C51.2 R94.1 U6.1(VSPI)
GND: C45.1 C50.2 C51.1 C52.1 C53.1 C127.2 D7.A U6.7(TEST1) U6.8(TEST2) U6.13(GND) U6.33(TAB)
CS: R87.2 ; port CS
DIAG: U6.6(DIAG) ; port DIAG
DIN: R97.2 ; port DIN
HWLO: R98.2 ; port HWLO
ISNS5_N: R82.3 U6.20(ISNS_N)
ISNS5_P: R82.4 U6.21(ISNS_P)
OUT: C52.2 R84.2 T15.S T16.S T17.S T18.S T19.S U6.23(OUT) ; port OUT
OUTST: R99.2 ; port OUTST
SCK: R90.2 ; port SCK
SDI: R88.2 ; port SDI
SDO: R89.2 ; port SDO
VCC: D10.A R82.2 ; port VCC
NetC44_1: C44.1 U6.30(CP1P)
NetC44_2: C44.2 U6.31(CP1M)
NetC45_2: C45.2 C53.2 U6.12(V3V3)
NetC46_1: C46.1 C48.2
NetC46_2: C46.2 C49.1 C127.1 D10.C U6.25(VS)
NetC47_1: C47.1 U6.29(CP2M)
NetC47_2: C47.2 U6.28(CP2P)
NetC48_1: C48.1 U6.27(CP)
NetC49_2: C49.2 C50.1
NetD7_C: D7.C ZD3.C
NetR82_1: R82.1 R93.2 T15.D T16.D T17.D T18.D T19.D
NetR83_1: R83.1 R84.1 R86.1 R92.1 R95.1 R100.1 U6.24(HS_GATE) ZD3.A
NetR83_2: R83.2 T15.G
NetR86_2: R86.2 T16.G
NetR87_1: R87.1 U6.2(CSN)
NetR88_1: R88.1 U6.3(SDI)
NetR89_1: R89.1 U6.4(SDO)
NetR90_1: R90.1 U6.5(SCK)
NetR92_2: R92.2 T17.G
NetR93_1: R93.1 R96.2 U6.19(NTC)
NetR94_2: R94.2 R98.1 U6.10(HWLO)
NetR95_2: R95.2 T18.G
NetR96_1: R96.1 U6.18(NTC_M)
NetR97_1: R97.1 U6.9(DIN)
NetR99_1: R99.1 U6.15(OUTST)
NetR100_2: R100.2 T19.G

Not connected (* = marked no-connect by the designer): U6 11* 14* 16* 17* 22* 26* 32*

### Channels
U_GroupA/U_VNF1248+5F8_A1: designators end in A; ports CS=SPI9_CS0 DIAG=DIAG_A DIN=DI_A2 HWLO=HWLO_A2 OUT=OUT_A2 OUTST=OUTST_A2 SCK=SPI9_SCK SDI=SPI9_MOSI SDO=SPI9_MISO VCC=VCCA
U_GroupB/U_VNF1248+5F8_B1: designators end in B; ports CS=SPI2_CS1 DIAG=DIAG_B DIN=DI_B2 HWLO=HWLO_B2 OUT=OUT_B2 OUTST=OUTST_B2 SCK=SPI2_SCK SDI=SPI2_MOSI SDO=SPI2_MISO VCC=VCCB

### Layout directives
differential pair: ISNS5_N_U_VNF1248+5F8_A1, ISNS5_P_U_VNF1248+5F8_A1

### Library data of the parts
C44 C47 C49 C50 = 470nF/50V_10%_0603: as C34 on sheet VNF1248+8F8
C45 = 220nF/50V_10%_0603: as C35 on sheet VNF1248+8F8
C46 C48 = 1uF/50V_10%_0603: as C36 on sheet VNF1248+8F8
C51 = 100nF/50V_10%_0603: as C41 on sheet VNF1248+8F8
C52 = 10nF/50V_10%_0603: as C42 on sheet VNF1248+8F8
C53 = 1uF/16V_10%_0603: as C43 on sheet VNF1248+8F8
C127 = 22uF/50V_20%_CES_D_6.3: as C126 on sheet VNF1248+8F8
D7 = BAT54-Y: Automotive small signal Schottky diodes; pin to pad: A>1 C>3; Forward Drop: 0,5V; T.Min: -40C; T.Max: 150C; Value: 40V; Current: 0.3A
D10 = STPS1L40-Y: as D9 on sheet VNF1248+8F8
R82 = CurrentShunt_15W_5930: as R60 on sheet VNF1248+8F8
R83 R86 R92 R95 R100 = 1R/0.1W_5%_0603: Resistor SMD; Tolerance: 5%; Power: 0.1W
R84 R94 = 47k/0.1W_5%_0603: Resistor SMD; Tolerance: 5%; Power: 0.1W
R87 R97-R99 = 2k7/0.1W_5%_0603: Resistor SMD; Tolerance: 5%; Power: 0.1W
R88 R90 = 5k6/0.1W_5%_0603: Resistor SMD; Tolerance: 5%; Power: 0.1W
R89 = 180R/0.1W_5%_0603: as R69 on sheet VNF1248+8F8
R93 = NTC: Model: B57321V2103J060
R96 = 10k/0.1W_5%_0603: as R76 on sheet VNF1248+8F8
T15-T19 = STL059N4S8AG: as T7 on sheet VNF1248+8F8
ZD3 = 5,6V/SOT-323: 5,6V Zener Diode; pin to pad: A>1 C>3; Power Rating: 200mW; T.Min: -65C; T.Max: 200C

## Sheet VNF1248+3F8.SchDoc: ST PDU - VNF1248 + 3xF8
size A4; Author: EMEA - ADG - M&A; Organization: STMicroelectronics; Address1: Pobrezni 3; Address2: 186 00  Prague 8; Address3: Czech Republic; Revision: 2.3; SheetNumber: 5; SheetTotal: 14
Used 6 times, as channels U_GroupA/U_VNF1248+3F8_A1, U_GroupA/U_VNF1248+3F8_A2, U_GroupA/U_VNF1248+3F8_A3, U_GroupB/U_VNF1248+3F8_B1, U_GroupB/U_VNF1248+3F8_B2, U_GroupB/U_VNF1248+3F8_B3. Parts and nets are listed once, with the designators drawn on the sheet.
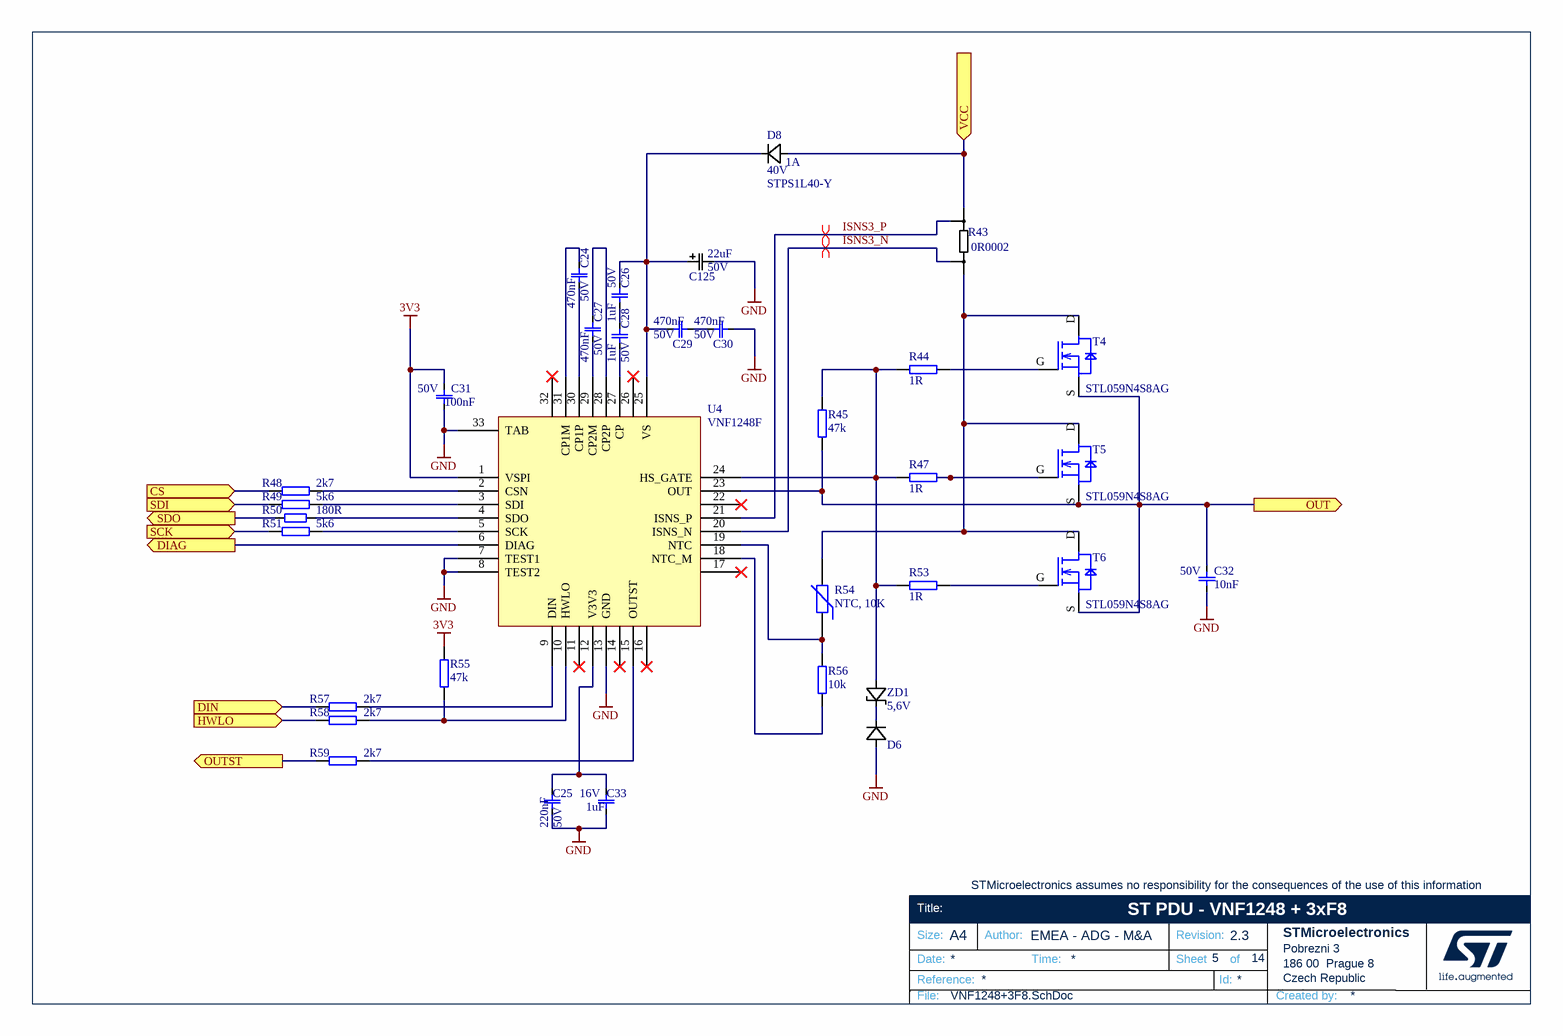
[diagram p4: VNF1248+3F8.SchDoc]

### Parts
C24  Voltage: 50V  [C0603_ROUND]  (hidden comment: 470nF)
C25  Voltage: 50V  [C0603_ROUND]  (hidden comment: 220nF)
C26  Voltage: 50V  [C0603_ROUND]  (hidden comment: 1uF)
C27  Voltage: 50V  [C0603_ROUND]  (hidden comment: 470nF)
C28  Voltage: 50V  [C0603_ROUND]  (hidden comment: 1uF)
C29  Voltage: 50V  [C0603_ROUND]  (hidden comment: 470nF)
C30  Voltage: 50V  [C0603_ROUND]  (hidden comment: 470nF)
C31  Voltage: 50V  [C0603_ROUND]  (hidden comment: 100nF)
C32  Voltage: 50V  [C0603_ROUND]  (hidden comment: 10nF)
C33  Voltage: 16V  [C0603_ROUND]  (hidden comment: 1uF)
C125  Voltage: 50V  [C_EL 6.3x6.1mm VP]  (hidden comment: 22uF)
D6  BAT54-Y  [SOT323-3L_STM]  (value not drawn)
D8  value 40V  Current: 1A  [SOD123FLAT_STM]  (hidden comment: STPS1L40-Y)
R43  0R0002  [R Shunt 3921]
R44  1R  [R0603_round]
R45  47k  [R0603_round]
R47  1R  [R0603_round]
R48  2k7  [R0603_round]
R49  5k6  [R0603_round]
R50  180R  [R0603_round]
R51  5k6  [R0603_round]
R53  1R  [R0603_round]
R54  value NTC, 10K  [R0603_round]  (hidden comment: NTC)
R55  47k  [R0603_round]
R56  10k  [R0603_round]
R57  2k7  [R0603_round]
R58  2k7  [R0603_round]
R59  2k7  [R0603_round]
T4  value STL059N4S8AG  [Powerflat_5x6_Single_island]  (hidden comment: NMOS)
T5  value STL059N4S8AG  [Powerflat_5x6_Single_island]  (hidden comment: NMOS)
T6  value STL059N4S8AG  [Powerflat_5x6_Single_island]  (hidden comment: NMOS)
U4  VNF1248F  [QFN32L_5x5_STM-M]
ZD1  value 5,6V  [SOT323-3L_STM]  (hidden comment: 5,6V/SOT-323)

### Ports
CS (in, see GroupA[1B]), DIAG (out, see GroupA[1B], L99SP08[1B], VNF1248+5F8[1C], VNF1248+8F8[1C]), DIN (in, see GroupA[1B]), HWLO (in, see GroupA[1B]), OUT (out, see GroupA[2B]), OUTST (out, see GroupA[1B]), SCK (in, see GroupA[1B], VNF1248+5F8[1C], VNF1248+8F8[1C]), SDI (in, see GroupA[1B], VNF1248+5F8[1B], VNF1248+8F8[1B]), SDO (out, see GroupA[1B], VNF1248+5F8[1C], VNF1248+8F8[1C]), VCC (in, see GroupA[2B], L99SP08[2A], VNF9D1M5Q[3A], VNF9Q20SF[3A], VNF1248+5F8[3A], VNF1248+8F8[2A])

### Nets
3V3: C31.2 R55.1 U4.1(VSPI)
GND: C25.1 C30.2 C31.1 C32.1 C33.1 C125.2 D6.A U4.7(TEST1) U4.8(TEST2) U4.13(GND) U4.33(TAB)
CS: R48.2 ; port CS
DIAG: U4.6(DIAG) ; port DIAG
DIN: R57.2 ; port DIN
HWLO: R58.2 ; port HWLO
ISNS3_N: R43.3 U4.20(ISNS_N)
ISNS3_P: R43.4 U4.21(ISNS_P)
OUT: C32.2 R45.2 T4.S T5.S T6.S U4.23(OUT) ; port OUT
OUTST: R59.2 ; port OUTST
SCK: R51.2 ; port SCK
SDI: R49.2 ; port SDI
SDO: R50.2 ; port SDO
VCC: D8.A R43.2 ; port VCC
NetC24_1: C24.1 U4.30(CP1P)
NetC24_2: C24.2 U4.31(CP1M)
NetC25_2: C25.2 C33.2 U4.12(V3V3)
NetC26_1: C26.1 C28.2
NetC26_2: C26.2 C29.1 C125.1 D8.C U4.25(VS)
NetC27_1: C27.1 U4.29(CP2M)
NetC27_2: C27.2 U4.28(CP2P)
NetC28_1: C28.1 U4.27(CP)
NetC29_2: C29.2 C30.1
NetD6_C: D6.C ZD1.C
NetR43_1: R43.1 R54.2 T4.D T5.D T6.D
NetR44_1: R44.1 R45.1 R47.2 R53.1 U4.24(HS_GATE) ZD1.A
NetR44_2: R44.2 T4.G
NetR47_1: R47.1 T5.G
NetR48_1: R48.1 U4.2(CSN)
NetR49_1: R49.1 U4.3(SDI)
NetR50_1: R50.1 U4.4(SDO)
NetR51_1: R51.1 U4.5(SCK)
NetR53_2: R53.2 T6.G
NetR54_1: R54.1 R56.2 U4.19(NTC)
NetR55_2: R55.2 R58.1 U4.10(HWLO)
NetR56_1: R56.1 U4.18(NTC_M)
NetR57_1: R57.1 U4.9(DIN)
NetR59_1: R59.1 U4.15(OUTST)

Not connected (* = marked no-connect by the designer): U4 11* 14* 16* 17* 22* 26* 32*

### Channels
U_GroupA/U_VNF1248+3F8_A1: designators end in A; ports CS=SPI9_CS2 DIAG=DIAG_A DIN=DI_A3 HWLO=HWLO_A3 OUT=OUT_A3 OUTST=OUTST_A3 SCK=SPI9_SCK SDI=SPI9_MOSI SDO=SPI9_MISO VCC=VCCA
U_GroupA/U_VNF1248+3F8_A2: designators end in B; ports CS=SPI9_CS4 DIAG=DIAG_A DIN=DI_A4 HWLO=HWLO_A4 OUT=OUT_A4 OUTST=OUTST_A4 SCK=SPI9_SCK SDI=SPI9_MOSI SDO=SPI9_MISO VCC=VCCA
U_GroupA/U_VNF1248+3F8_A3: designators end in C; ports CS=SPI9_CS5 DIAG=DIAG_A DIN=DI_A5 HWLO=HWLO_A5 OUT=OUT_A5 OUTST=OUTST_A5 SCK=SPI9_SCK SDI=SPI9_MOSI SDO=SPI9_MISO VCC=VCCA
U_GroupB/U_VNF1248+3F8_B1: designators end in D; ports CS=SPI2_CS3 DIAG=DIAG_B DIN=DI_B3 HWLO=HWLO_B3 OUT=OUT_B3 OUTST=OUTST_B3 SCK=SPI2_SCK SDI=SPI2_MOSI SDO=SPI2_MISO VCC=VCCB
U_GroupB/U_VNF1248+3F8_B2: designators end in E; ports CS=SPI2_CS4 DIAG=DIAG_B DIN=DI_B4 HWLO=HWLO_B4 OUT=OUT_B4 OUTST=OUTST_B4 SCK=SPI2_SCK SDI=SPI2_MOSI SDO=SPI2_MISO VCC=VCCB
U_GroupB/U_VNF1248+3F8_B3: designators end in F; ports CS=SPI2_CS2 DIAG=DIAG_B DIN=DI_B5 HWLO=HWLO_B5 OUT=OUT_B5 OUTST=OUTST_B5 SCK=SPI2_SCK SDI=SPI2_MOSI SDO=SPI2_MISO VCC=VCCB

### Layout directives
differential pair: ISNS3_N_U_VNF1248+3F8_A1, ISNS3_P_U_VNF1248+3F8_A1

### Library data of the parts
C24 C27 C29 C30 = 470nF/50V_10%_0603: as C34 on sheet VNF1248+8F8
C25 = 220nF/50V_10%_0603: as C35 on sheet VNF1248+8F8
C26 C28 = 1uF/50V_10%_0603: as C36 on sheet VNF1248+8F8
C31 = 100nF/50V_10%_0603: as C41 on sheet VNF1248+8F8
C32 = 10nF/50V_10%_0603: as C42 on sheet VNF1248+8F8
C33 = 1uF/16V_10%_0603: as C43 on sheet VNF1248+8F8
C125 = 22uF/50V_20%_CES_D_6.3: as C126 on sheet VNF1248+8F8
D6 = BAT54-Y: Automotive small signal Schottky diodes; pin to pad: A>1 C>3; Forward Drop: 0,5V; T.Min: -40C; T.Max: 150C; Value: 40V; Current: 0.3A
D8 = STPS1L40-Y: as D9 on sheet VNF1248+8F8
R43 = CurrentShunt_9W_3921: High current shunt size 3921; Voltage: 150V; Power Rating Per Resistor: 9W; T.Min: -55C; T.Max: 170C
R44 R47 R53 = 1R/0.1W_5%_0603: Resistor SMD; Tolerance: 5%; Power: 0.1W
R45 R55 = 47k/0.1W_5%_0603: Resistor SMD; Tolerance: 5%; Power: 0.1W
R48 R57-R59 = 2k7/0.1W_5%_0603: Resistor SMD; Tolerance: 5%; Power: 0.1W
R49 R51 = 5k6/0.1W_5%_0603: Resistor SMD; Tolerance: 5%; Power: 0.1W
R50 = 180R/0.1W_5%_0603: as R69 on sheet VNF1248+8F8
R54 = NTC: Model: B57321V2103J060
R56 = 10k/0.1W_5%_0603: as R76 on sheet VNF1248+8F8
T4-T6 = STL059N4S8AG: as T7 on sheet VNF1248+8F8
ZD1 = 5,6V/SOT-323: 5,6V Zener Diode; pin to pad: A>1 C>3; Power Rating: 200mW; T.Min: -65C; T.Max: 200C

## Sheet VNF9D1M5Q.SchDoc: ST PDU - VNF9D1M5Q
size A4; Author: EMEA - ADG - M&A; Organization: STMicroelectronics; Address1: Pobrezni 3; Address2: 186 00  Prague 8; Address3: Czech Republic; Revision: 2.3; SheetNumber: 7; SheetTotal: 14
Used 4 times, as channels U_GroupA/U_VNF9D1M5Q_A1, U_GroupA/U_VNF9D1M5Q_A2, U_GroupB/U_VNF9D1M5Q_B1, U_GroupB/U_VNF9D1M5Q_B2. Parts and nets are listed once, with the designators drawn on the sheet.
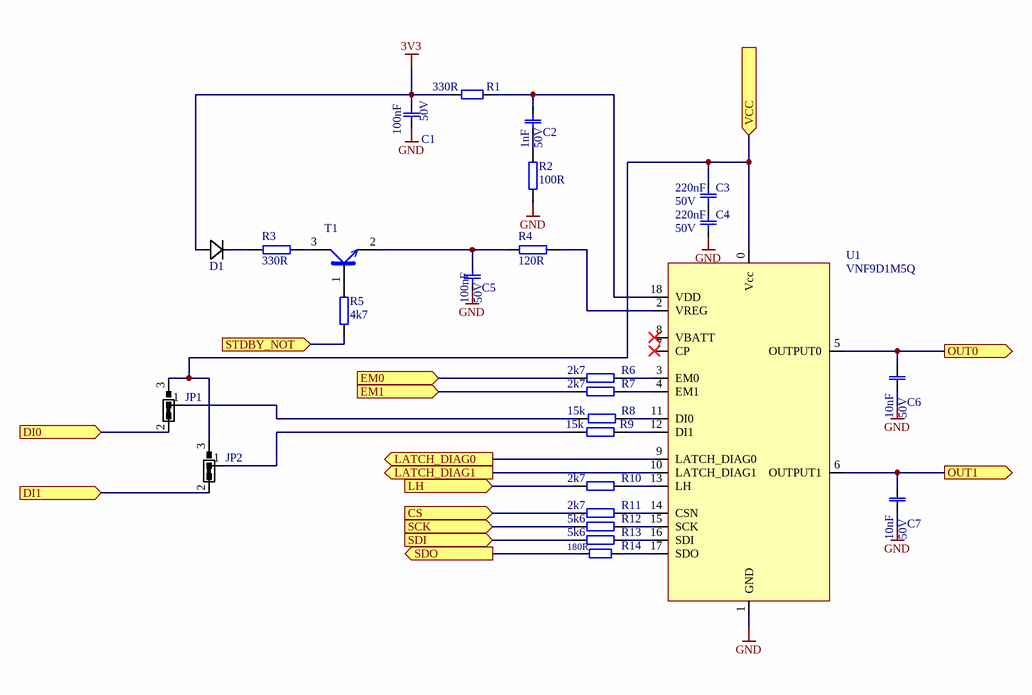
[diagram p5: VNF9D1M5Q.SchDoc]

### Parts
C1  Voltage: 50V  [C0603_ROUND]  (hidden comment: 100nF)
C2  Voltage: 50V  [C0603_ROUND]  (hidden comment: 1nF)
C3  Voltage: 50V  [C0603_ROUND]  (hidden comment: 220nF)
C4  Voltage: 50V  [C0603_ROUND]  (hidden comment: 220nF)
C5  Voltage: 50V  [C0603_ROUND]  (hidden comment: 100nF)
C6  Voltage: 50V  [C0603_ROUND]  (hidden comment: 10nF)
C7  Voltage: 50V  [C0603_ROUND]  (hidden comment: 10nF)
D1  BAT54-Y  [SOT323-3L_STM]  (value not drawn)
JP1  Always ON selector  [R0603_3JUMP]  (value not drawn)
JP2  Always ON selector  [R0603_3JUMP]  (value not drawn)
R1  330R  [R0805_ROUND]
R2  100R  [R0603_round]
R3  330R  [R0603_round]
R4  120R  [R0603_round]
R5  4k7  [R0603_round]
R6  2k7  [R0603_round]
R7  2k7  [R0603_round]
R8  15k  [R0603_round]
R9  15k  [R0603_round]
R10  2k7  [R0603_round]
R11  2k7  [R0603_round]
R12  5k6  [R0603_round]
R13  5k6  [R0603_round]
R14  180R  [R0603_round]
T1  BC847  [SOT323-3L_STM]  (value not drawn)
U1  VNF9D1M5Q  [PQFN 7x8.5]

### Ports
CS (in, see GroupA[4B]), DI0 (in, see GroupA[4A]), DI1 (in, see GroupA[4A]), EM0 (in, see GroupA[4A]), EM1 (in, see GroupA[4A]), LATCH_DIAG0 (out, see GroupA[4A]), LATCH_DIAG1 (out, see GroupA[4A]), LH (in, see GroupA[4A]), OUT0 (out, see GroupA[5A]), OUT1 (out, see GroupA[5B]), SCK (in, see GroupA[4B], L99SP08[2C], VNF9Q20SF[1C]), SDI (in, see GroupA[4B], L99SP08[2C], VNF9Q20SF[1C]), SDO (out, see GroupA[4B], L99SP08[2C], VNF9Q20SF[1C]), STDBY_NOT (in, see GroupA[4B], VNF9Q20SF[1C]), VCC (in, see GroupA[5A], L99SP08[2A], VNF9Q20SF[3A], VNF1248+3F8[3A], VNF1248+5F8[3A], VNF1248+8F8[2A])

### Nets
3V3: C1.2 D1.A R1.1
GND: C1.1 C4.1 C5.1 C6.1 C7.1 R2.2 U1.1(GND)
CS: R11.2 ; port CS
DI0: JP1.2 ; port DI0
DI1: JP2.2 ; port DI1
EM0: R6.2 ; port EM0
EM1: R7.2 ; port EM1
LATCH_DIAG0: U1.9(LATCH_DIAG0) ; port LATCH_DIAG0
LATCH_DIAG1: U1.10(LATCH_DIAG1) ; port LATCH_DIAG1
LH: R10.2 ; port LH
OUT0: C6.2 U1.5(OUTPUT0) ; port OUT0
OUT1: C7.2 U1.6(OUTPUT1) ; port OUT1
SCK: R12.2 ; port SCK
SDI: R13.2 ; port SDI
SDO: R14.1 ; port SDO
STDBY_NOT: R5.2 ; port STDBY_NOT
VCC: C3.2 JP1.3 JP2.3 U1.0(Vcc) ; port VCC
NetC2_1: C2.1 R2.1
NetC2_2: C2.2 R1.2 U1.18(VDD)
NetC3_1: C3.1 C4.2
NetC5_2: C5.2 R4.1 T1.2(E)
NetD1_C: D1.C R3.1
NetJP1_1: JP1.1 R8.2
NetJP2_1: JP2.1 R9.2
NetR3_2: R3.2 T1.3(C)
NetR4_2: R4.2 U1.2(VREG)
NetR5_1: R5.1 T1.1(B)
NetR6_1: R6.1 U1.3(EM0)
NetR7_1: R7.1 U1.4(EM1)
NetR8_1: R8.1 U1.11(DI0)
NetR9_1: R9.1 U1.12(DI1)
NetR10_1: R10.1 U1.13(LH)
NetR11_1: R11.1 U1.14(CSN)
NetR12_1: R12.1 U1.15(SCK)
NetR13_1: R13.1 U1.16(SDI)
NetR14_2: R14.2 U1.17(SDO)

Not connected (* = marked no-connect by the designer): U1 7(CP)* 8(VBATT)*

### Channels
U_GroupA/U_VNF9D1M5Q_A1: designators end in A; ports CS=SPI0_CS6 DI0=EN_A7 DI1=EN_A6 EM0=EM0_A6 EM1=EM1_A6 LATCH_DIAG0=DIAG_A LATCH_DIAG1=DIAG_A LH=LH_A6 OUT0=OUT_A7 OUT1=OUT_A6 SCK=SPI0_SCK SDI=SPI0_MOSI SDO=SPI0_MISO STDBY_NOT=STDBY_NOT_A VCC=VCCA
U_GroupA/U_VNF9D1M5Q_A2: designators end in B; ports CS=SPI0_CS0 DI0=EN_A9 DI1=EN_A8 EM0=EM0_A8 EM1=EM1_A8 LATCH_DIAG0=DIAG_A LATCH_DIAG1=DIAG_A LH=LH_A8 OUT0=OUT_A9 OUT1=OUT_A8 SCK=SPI0_SCK SDI=SPI0_MOSI SDO=SPI0_MISO STDBY_NOT=STDBY_NOT_A VCC=VCCA
U_GroupB/U_VNF9D1M5Q_B1: designators end in C; ports CS=SPI5_CS0 DI0=EN_B7 DI1=EN_B6 EM0=EM0_B6 EM1=EM1_B6 LATCH_DIAG0=DIAG_B LATCH_DIAG1=DIAG_B LH=LH_B6 OUT0=OUT_B7 OUT1=OUT_B6 SCK=SPI5_SCK SDI=SPI5_MOSI SDO=SPI5_MISO STDBY_NOT=STDBY_NOT_B VCC=VCCB
U_GroupB/U_VNF9D1M5Q_B2: designators end in D; ports CS=SPI5_CS6 DI0=EN_B9 DI1=EN_B8 EM0=EM0_B8 EM1=EM1_B8 LATCH_DIAG0=DIAG_B LATCH_DIAG1=DIAG_B LH=LH_B8 OUT0=OUT_B9 OUT1=OUT_B8 SCK=SPI5_SCK SDI=SPI5_MOSI SDO=SPI5_MISO STDBY_NOT=STDBY_NOT_B VCC=VCCB

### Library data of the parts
C1 C5 = 100nF/50V_10%_0603: as C41 on sheet VNF1248+8F8
C2 = 1nF/50V_10%_0603: 1nF Ceramic capacitor; Tolerance: 10%; T.Min: -55C; T.Max: 125C; Type: X7R
C3 C4 = 220nF/50V_10%_0603: as C35 on sheet VNF1248+8F8
C6 C7 = 10nF/50V_10%_0603: as C42 on sheet VNF1248+8F8
D1 = BAT54-Y: Automotive small signal Schottky diodes; pin to pad: A>1 C>3; Forward Drop: 0,5V; T.Min: -40C; T.Max: 150C; Value: 40V; Current: 0.3A
JP1 JP2 = JUMP_3_PIN
R1 = 330R/150V_1%_0805: Resistor SMD 0805; Tolerance: 1%; Voltage: 150V; Power Rating Per Resistor: 125mW; T.Min: -55C; T.Max: 155C
R2 = 100R/0.1W_5%_0603: Resistor SMD; Tolerance: 5%; Power: 0.1W
R3 = 330R/0.1W_5%_0603: Resistor SMD; Tolerance: 5%; Power: 0.1W
R4 = 120R/0.1W_5%_0603: Resistor SMD; Tolerance: 5%; Power: 0.1W
R5 = 4k7/0.1W_5%_0603: Resistor SMD; Tolerance: 5%; Power: 0.1W
R6 R7 R10 R11 = 2k7/0.1W_5%_0603: Resistor SMD; Tolerance: 5%; Power: 0.1W
R8 R9 = 15k/0.1W_5%_0603: Resistor SMD; Tolerance: 5%; Power: 0.1W
R12 R13 = 5k6/0.1W_5%_0603: Resistor SMD; Tolerance: 5%; Power: 0.1W
R14 = 180R/0.1W_5%_0603: as R69 on sheet VNF1248+8F8
T1 = BC847: NPN

## Sheet L99SP08.SchDoc: ST PDU - L99SP08
size A4; Author: EMEA - ADG - M&A; Organization: STMicroelectronics; Address1: Pobrezni 3; Address2: 186 00  Prague 8; Address3: Czech Republic; Revision: 2.3; SheetNumber: 8; SheetTotal: 14
Used 2 times, as channels U_GroupA/U_L99SP08_A1, U_GroupB/U_L99SP08_B1. Parts and nets are listed once, with the designators drawn on the sheet.
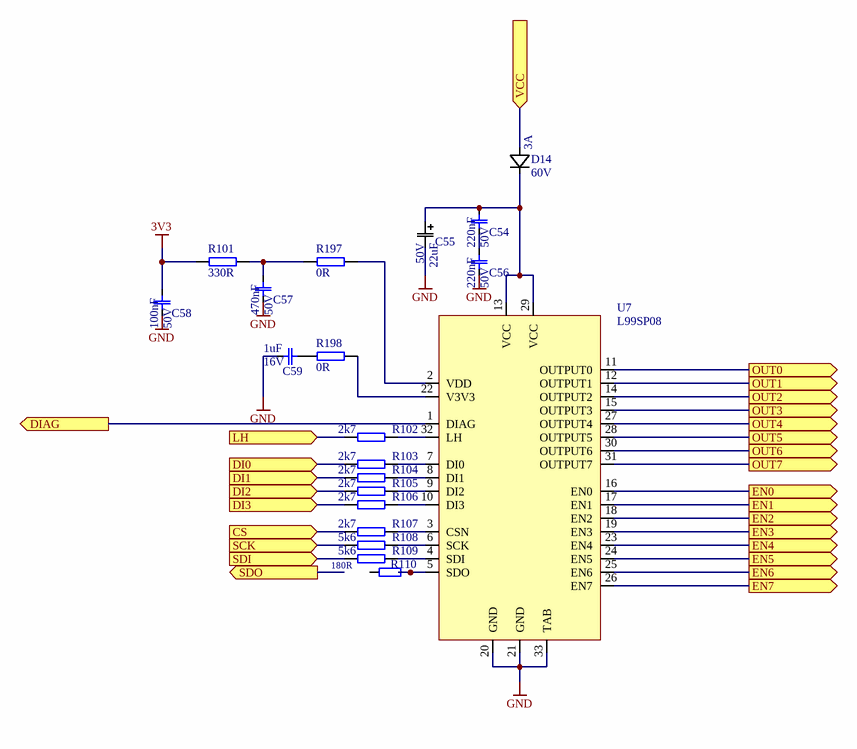
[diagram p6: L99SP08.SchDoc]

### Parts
C54  Voltage: 50V  [C0603_ROUND]  (hidden comment: 220nF)
C55  Voltage: 50V  [C_EL 6.3x6.1mm VP]  (hidden comment: 22uF)
C56  Voltage: 50V  [C0603_ROUND]  (hidden comment: 220nF)
C57  Voltage: 50V  [C0603_ROUND]  (hidden comment: 470nF)
C58  Voltage: 50V  [C0603_ROUND]  (hidden comment: 100nF)
C59  Voltage: 16V  [C0603_ROUND]  (hidden comment: 1uF)
D14  value 60V  Current: 3A  [SOD128FLAT_STM]  (hidden comment: STPS360-Y)
R101  330R  [R0603_round]
R102  2k7  [R0603_round]
R103  2k7  [R0603_round]
R104  2k7  [R0603_round]
R105  2k7  [R0603_round]
R106  2k7  [R0603_round]
R107  2k7  [R0603_round]
R108  5k6  [R0603_round]
R109  5k6  [R0603_round]
R110  180R  [R0603_round]
R197  0R  [R0603_round]
R198  0R  [R0603_round]
U7  L99SP08  [QFN32L_5x5_STM-M]

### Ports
CS (in, see GroupA[7B]), DI0 (in, see GroupA[7B]), DI1 (in, see GroupA[7B]), DI2 (in, see GroupA[7B]), DI3 (in, see GroupA[7B]), DIAG (out, see GroupA[7B], VNF1248+3F8[1C], VNF1248+5F8[1C], VNF1248+8F8[1C]), EN0 (out, see GroupA[8B]), EN1 (out, see GroupA[8B]), EN2 (out, see GroupA[8B]), EN3 (out, see GroupA[8B]), EN4 (out, see GroupA[8B]), EN5 (out, see GroupA[8B]), EN6 (out, see GroupA[8B]), EN7 (out, see GroupA[8B]), LH (in, see GroupA[7B]), OUT0 (out, see GroupA[8B]), OUT1 (out, see GroupA[8B]), OUT2 (out, see GroupA[8B]), OUT3 (out, see GroupA[8B]), OUT4 (out, see GroupA[8B]), OUT5 (out, see GroupA[8B]), OUT6 (out, see GroupA[8B]), OUT7 (out, see GroupA[8B]), SCK (in, see GroupA[7B], VNF9D1M5Q[2C], VNF9Q20SF[1C]), SDI (in, see GroupA[7B], VNF9D1M5Q[2C], VNF9Q20SF[1C]), SDO (out, see GroupA[7B], VNF9D1M5Q[2C], VNF9Q20SF[1C]), VCC (in, see GroupA[7B], VNF9D1M5Q[3A], VNF9Q20SF[3A], VNF1248+3F8[3A], VNF1248+5F8[3A], VNF1248+8F8[2A])

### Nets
3V3: C58.2 R101.1
GND: C55.2 C56.1 C57.1 C58.1 C59.1 U7.20(GND) U7.21(GND) U7.33(TAB)
CS: R107.2 ; port CS
DI0: R103.2 ; port DI0
DI1: R104.2 ; port DI1
DI2: R105.2 ; port DI2
DI3: R106.2 ; port DI3
DIAG: U7.1(DIAG) ; port DIAG
EN0: U7.16(EN0) ; port EN0
EN1: U7.17(EN1) ; port EN1
EN2: U7.18(EN2) ; port EN2
EN3: U7.19(EN3) ; port EN3
EN4: U7.23(EN4) ; port EN4
EN5: U7.24(EN5) ; port EN5
EN6: U7.25(EN6) ; port EN6
EN7: U7.26(EN7) ; port EN7
LH: R102.2 ; port LH
OUT0: U7.11(OUTPUT0) ; port OUT0
OUT1: U7.12(OUTPUT1) ; port OUT1
OUT2: U7.14(OUTPUT2) ; port OUT2
OUT3: U7.15(OUTPUT3) ; port OUT3
OUT4: U7.27(OUTPUT4) ; port OUT4
OUT5: U7.28(OUTPUT5) ; port OUT5
OUT6: U7.30(OUTPUT6) ; port OUT6
OUT7: U7.31(OUTPUT7) ; port OUT7
SCK: R108.2 ; port SCK
SDI: R109.2 ; port SDI
VCC: D14.A ; port VCC
NetC54_1: C54.1 C56.2
NetC54_2: C54.2 C55.1 D14.C U7.13(VCC) U7.29(VCC)
NetC57_2: C57.2 R101.2 R197.2
NetC59_2: C59.2 R198.2
NetR102_1: R102.1 U7.32(LH)
NetR103_1: R103.1 U7.7(DI0)
NetR104_1: R104.1 U7.8(DI1)
NetR105_1: R105.1 U7.9(DI2)
NetR106_1: R106.1 U7.10(DI3)
NetR107_1: R107.1 U7.3(CSN)
NetR108_1: R108.1 U7.6(SCK)
NetR109_1: R109.1 U7.4(SDI)
NetR110_2: R110.2 U7.5(SDO)
NetR197_1: R197.1 U7.2(VDD)
NetR198_1: R198.1 U7.22(V3V3)

Not connected (* = marked no-connect by the designer): R110 1

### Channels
U_GroupA/U_L99SP08_A1: designators end in A; ports CS=SPI0_CS1 DI0=DI0_A14 DI1=DI1_A14 DI2=DI2_A14 DI3=DI3_A14 DIAG=DIAG_A EN0=EN_A6 EN1=EN_A7 EN2=EN_A8 EN3=EN_A9 EN4=EN_A10 EN5=EN_A11 EN6=EN_A11 EN7=EN_A10 LH=LH_A14 OUT0=OUT_A6 OUT1=OUT_A7 OUT2=OUT_A8 OUT3=OUT_A9 OUT4=NetR111_2 OUT5=NetR112_2 OUT6=NetR113_2 OUT7=NetR114_2 SCK=SPI0_SCK SDI=SPI0_MOSI SDO=SPI0_MISO VCC=VCCA
U_GroupB/U_L99SP08_B1: designators end in B; ports CS=SPI5_CS3 DI0=DI0_B14 DI1=DI1_B14 DI2=DI2_B14 DI3=DI3_B14 DIAG=DIAG_B EN0=EN_B6 EN1=EN_B7 EN2=EN_B8 EN3=EN_B9 EN4=EN_B13 EN5=EN_B12 EN6=EN_B11 EN7=EN_B10 LH=LH_B14 OUT0=OUT_B6 OUT1=OUT_B7 OUT2=OUT_B8 OUT3=OUT_B9 OUT4=NetR115_2 OUT5=NetR116_2 OUT6=NetR117_2 OUT7=NetR118_2 SCK=SPI5_SCK SDI=SPI5_MOSI SDO=SPI5_MISO VCC=VCCB

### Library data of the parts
C54 C56 = 220nF/50V_10%_0603: as C35 on sheet VNF1248+8F8
C55 = 22uF/50V_20%_CES_D_6.3: 22uF Electrolytic capacitor (EEHZC1H220P); Tolerance: 20%; T.Min: -55C; T.Max: 125C; Type: Conductive Polymer Hybrid Aluminum Electrolytic Capacitor
C57 = 470nF/50V_10%_0603: as C34 on sheet VNF1248+8F8
C58 = 100nF/50V_10%_0603: as C41 on sheet VNF1248+8F8
C59 = 1uF/16V_10%_0603: as C43 on sheet VNF1248+8F8
D14 = STPS360-Y: 60V/3A Automotive Schottky Diode STPS360-Y
R101 = 330R/0.1W_5%_0603: Resistor SMD; Tolerance: 5%; Power: 0.1W
R102-R107 = 2k7/0.1W_5%_0603: Resistor SMD; Tolerance: 5%; Power: 0.1W
R108 R109 = 5k6/0.1W_5%_0603: Resistor SMD; Tolerance: 5%; Power: 0.1W
R110 = 180R/0.1W_5%_0603: as R69 on sheet VNF1248+8F8
R197 R198 = 0R/0.1W_5%_0603: Resistor SMD; Tolerance: 5%; Power: 0.1W
U7 = L99SP08: Octa channel Smart P-channel MOSFET device. Used for standby power with STi2Fuse devices

## Sheet VNF9Q20SF.SchDoc: ST PDU - VNF9Q20SF
size A4; Author: EMEA - ADG - M&A; Organization: STMicroelectronics; Address1: Pobrezni 3; Address2: 186 00  Prague 8; Address3: Czech Republic; Revision: 2.3; SheetNumber: 6; SheetTotal: 14
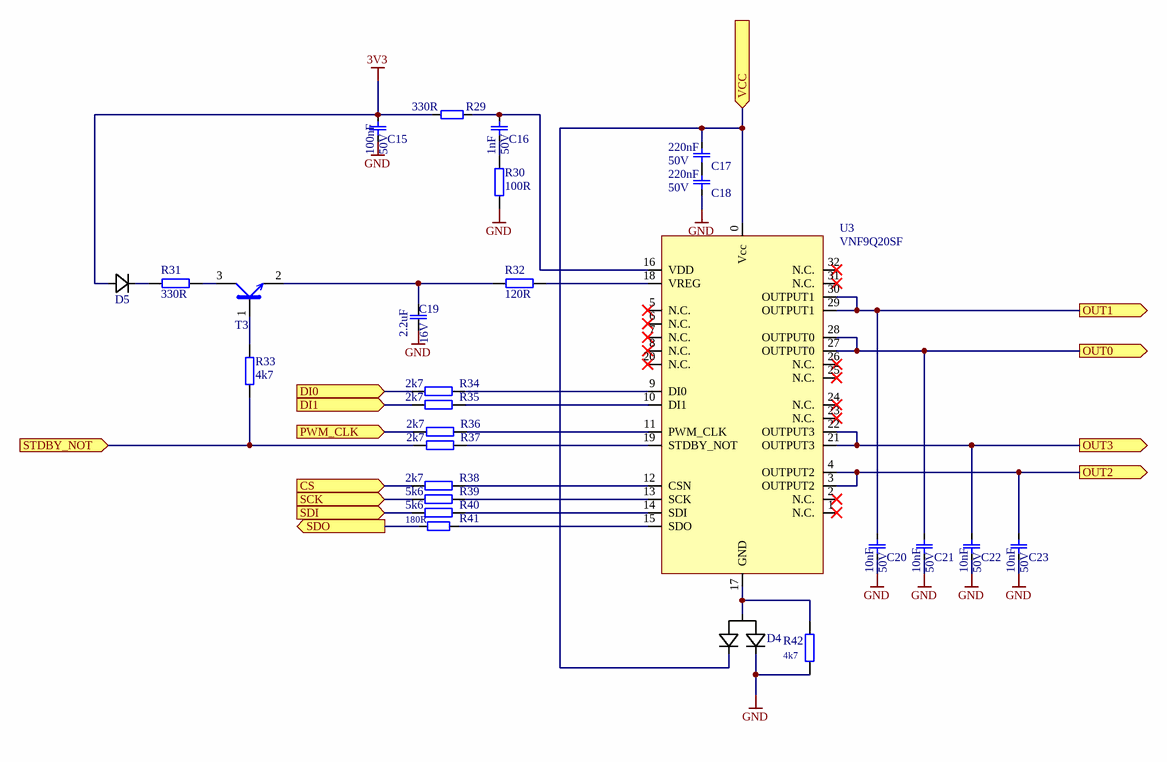
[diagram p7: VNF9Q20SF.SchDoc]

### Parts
C15  Voltage: 50V  [C0603_ROUND]  (hidden comment: 100nF)
C16  Voltage: 50V  [C0603_ROUND]  (hidden comment: 1nF)
C17  Voltage: 50V  [C0603_ROUND]  (hidden comment: 220nF)
C18  Voltage: 50V  [C0603_ROUND]  (hidden comment: 220nF)
C19  Voltage: 16V  [C0603_ROUND]  (hidden comment: 2.2uF)
C20  Voltage: 50V  [C0603_ROUND]  (hidden comment: 10nF)
C21  Voltage: 50V  [C0603_ROUND]  (hidden comment: 10nF)
C22  Voltage: 50V  [C0603_ROUND]  (hidden comment: 10nF)
C23  Voltage: 50V  [C0603_ROUND]  (hidden comment: 10nF)
D4  BAT54A  [SOT323-3L_STM]  (value not drawn)
D5  BAT54-Y  [SOT323-3L_STM]  (value not drawn)
R29  330R  [R0805_ROUND]
R30  100R  [R0603_round]
R31  330R  [R0603_round]
R32  120R  [R0603_round]
R33  4k7  [R0603_round]
R34  2k7  [R0603_round]
R35  2k7  [R0603_round]
R36  2k7  [R0603_round]
R37  2k7  [R0603_round]
R38  2k7  [R0603_round]
R39  5k6  [R0603_round]
R40  5k6  [R0603_round]
R41  180R  [R0603_round]
R42  4k7  [R0603_round]
T3  BC847  [SOT323-3L_STM]  (value not drawn)
U3  VNF9Q20SF  [QFN6x6_VN9D30_STM]

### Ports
CS (in, see GroupA[4C]), DI0 (in, see GroupA[4C]), DI1 (in, see GroupA[4C]), OUT0 (out, see GroupA[5C]), OUT1 (out, see GroupA[5C]), OUT2 (out, see GroupA[5C]), OUT3 (out, see GroupA[5C]), PWM_CLK (in, see GroupA[4C]), SCK (in, see GroupA[4C], L99SP08[2C], VNF9D1M5Q[2C]), SDI (in, see GroupA[4C], L99SP08[2C], VNF9D1M5Q[2C]), SDO (out, see GroupA[4C], L99SP08[2C], VNF9D1M5Q[2C]), STDBY_NOT (in, see GroupA[4C], VNF9D1M5Q[1B]), VCC (in, see GroupA[5C], L99SP08[2A], VNF9D1M5Q[3A], VNF1248+3F8[3A], VNF1248+5F8[3A], VNF1248+8F8[2A])

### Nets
3V3: C15.2 D5.A R29.1
GND: C15.1 C18.1 C19.1 C20.1 C21.1 C22.1 C23.1 D4.2 R30.2 R42.2
VCCA: C17.2 D4.1 U3.0(Vcc) ; port VCC
EN_A10: R35.2 ; port DI1
EN_A11: R34.2 ; port DI0
OUT_A10: C22.2 U3.21(OUTPUT3) U3.22(OUTPUT3) ; port OUT3
OUT_A11: C21.2 U3.27(OUTPUT0) U3.28(OUTPUT0) ; port OUT0
OUT_A12: C20.2 U3.29(OUTPUT1) U3.30(OUTPUT1) ; port OUT1
OUT_A13: C23.2 U3.3(OUTPUT2) U3.4(OUTPUT2) ; port OUT2
PWM_CLK_A: R36.2 ; port PWM_CLK
SPI0_CS2: R38.2 ; port CS
SPI0_MISO: R41.1 ; port SDO
SPI0_MOSI: R40.2 ; port SDI
SPI0_SCK: R39.2 ; port SCK
STDBY_NOT_A: R33.2 R37.2 ; port STDBY_NOT
NetC16_1: C16.1 R30.1
NetC16_2: C16.2 R29.2 U3.16(VDD)
NetC17_1: C17.1 C18.2
NetC19_2: C19.2 R32.1 T3.2(E)
NetD4_3: D4.3 R42.1 U3.17(GND)
NetD5_C: D5.C R31.1
NetR31_2: R31.2 T3.3(C)
NetR32_2: R32.2 U3.18(VREG)
NetR33_1: R33.1 T3.1(B)
NetR34_1: R34.1 U3.9(DI0)
NetR35_1: R35.1 U3.10(DI1)
NetR36_1: R36.1 U3.11(PWM_CLK)
NetR37_1: R37.1 U3.19(STDBY_NOT)
NetR38_1: R38.1 U3.12(CSN)
NetR39_1: R39.1 U3.13(SCK)
NetR40_1: R40.1 U3.14(SDI)
NetR41_2: R41.2 U3.15(SDO)

Not connected (* = marked no-connect by the designer): U3 1(N.C.)* 2(N.C.)* 5(N.C.)* 6(N.C.)* 7(N.C.)* 8(N.C.)* 20(N.C.)* 23(N.C.)* 24(N.C.)* 25(N.C.)* 26(N.C.)* 31(N.C.)* 32(N.C.)*

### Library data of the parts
C15 = 100nF/50V_10%_0603: as C41 on sheet VNF1248+8F8
C16 = 1nF/50V_10%_0603: as C2 on sheet VNF9D1M5Q
C17 C18 = 220nF/50V_10%_0603: as C35 on sheet VNF1248+8F8
C19 = 2.2uF/16V_10%_0603: 2.2uF Ceramic capacitor; Tolerance: 10%; T.Min: -55C; T.Max: 125C; Type: X7R
C20-C23 = 10nF/50V_10%_0603: as C42 on sheet VNF1248+8F8
D4 = BAT54A: Automotive small signal dual Schottky diodes with common anode; Forward Drop: 0,5V; T.Min: -40C; T.Max: 150C; Value: 40V; Current: 0.3A
D5 = BAT54-Y: Automotive small signal Schottky diodes; pin to pad: A>1 C>3; Forward Drop: 0,5V; T.Min: -40C; T.Max: 150C; Value: 40V; Current: 0.3A
R29 = 330R/150V_1%_0805: as R1 on sheet VNF9D1M5Q
R30 = 100R/0.1W_5%_0603: Resistor SMD; Tolerance: 5%; Power: 0.1W
R31 = 330R/0.1W_5%_0603: Resistor SMD; Tolerance: 5%; Power: 0.1W
R32 = 120R/0.1W_5%_0603: Resistor SMD; Tolerance: 5%; Power: 0.1W
R33 R42 = 4k7/0.1W_5%_0603: Resistor SMD; Tolerance: 5%; Power: 0.1W
R34-R38 = 2k7/0.1W_5%_0603: Resistor SMD; Tolerance: 5%; Power: 0.1W
R39 R40 = 5k6/0.1W_5%_0603: Resistor SMD; Tolerance: 5%; Power: 0.1W
R41 = 180R/0.1W_5%_0603: as R69 on sheet VNF1248+8F8
T3 = BC847: NPN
